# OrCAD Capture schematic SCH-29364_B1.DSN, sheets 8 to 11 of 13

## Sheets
8 C-06 BOOT CFG: size C
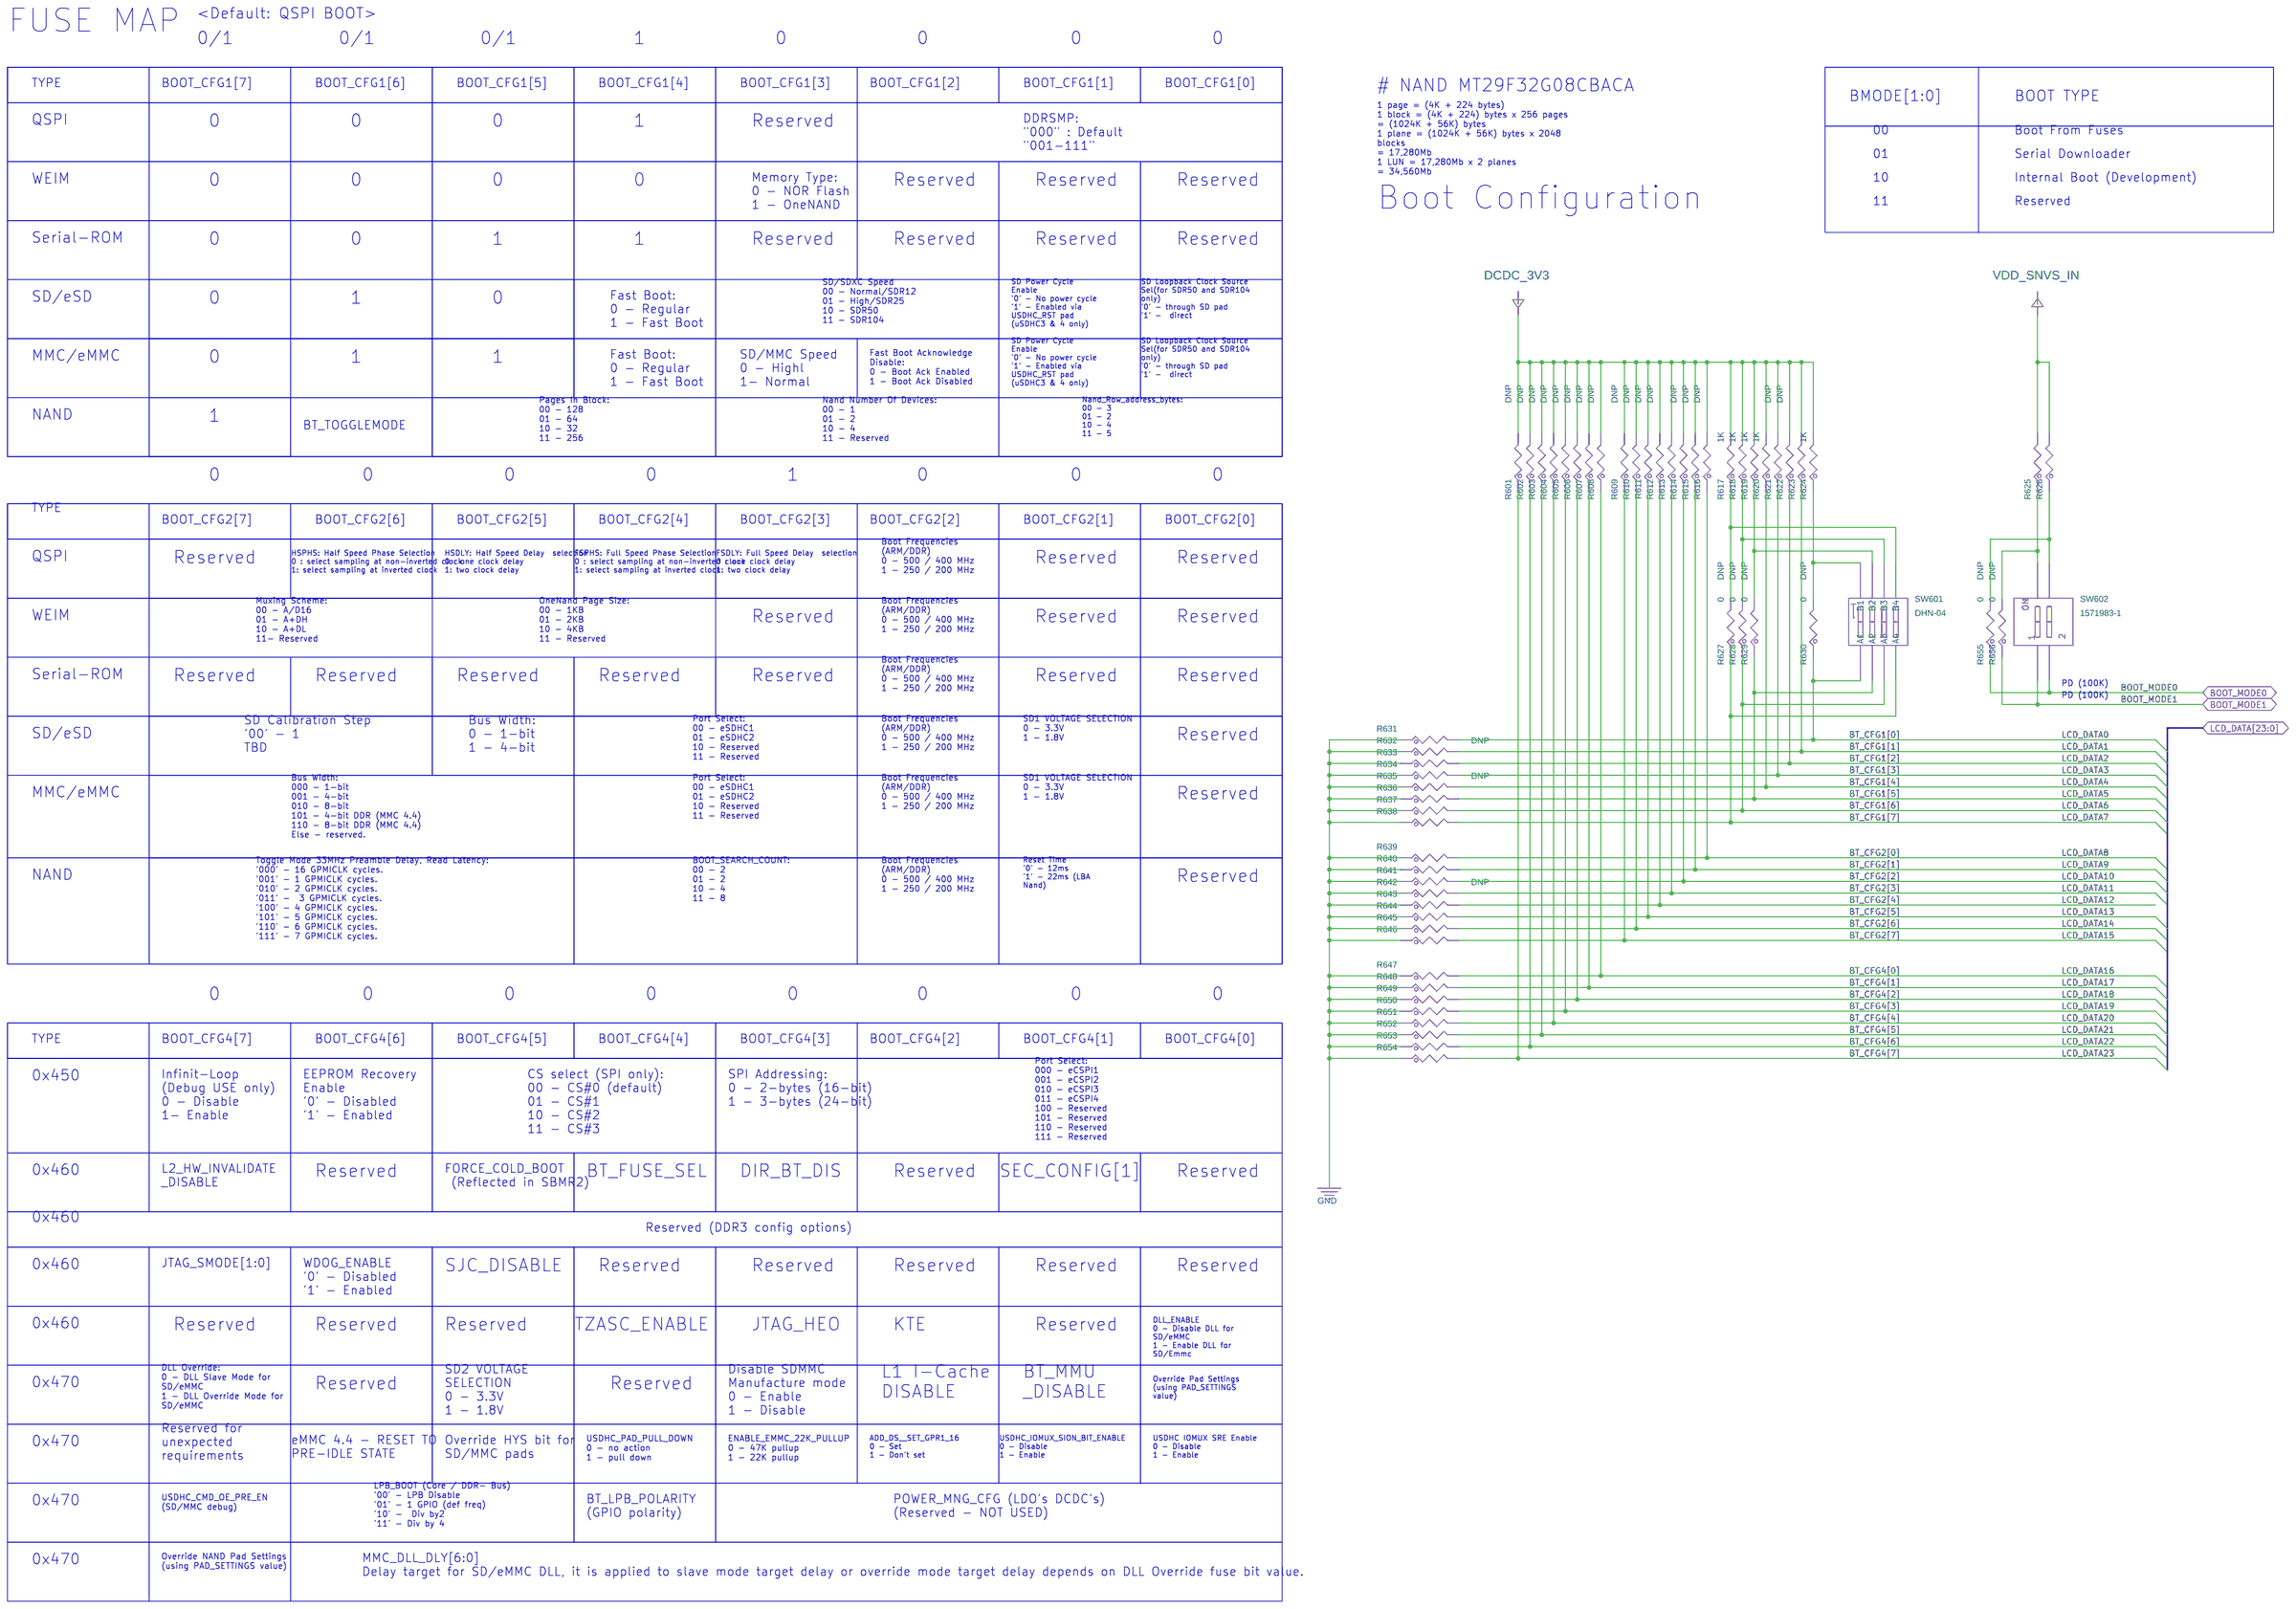
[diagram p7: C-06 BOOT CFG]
9 C-07 PWR MGR: size C
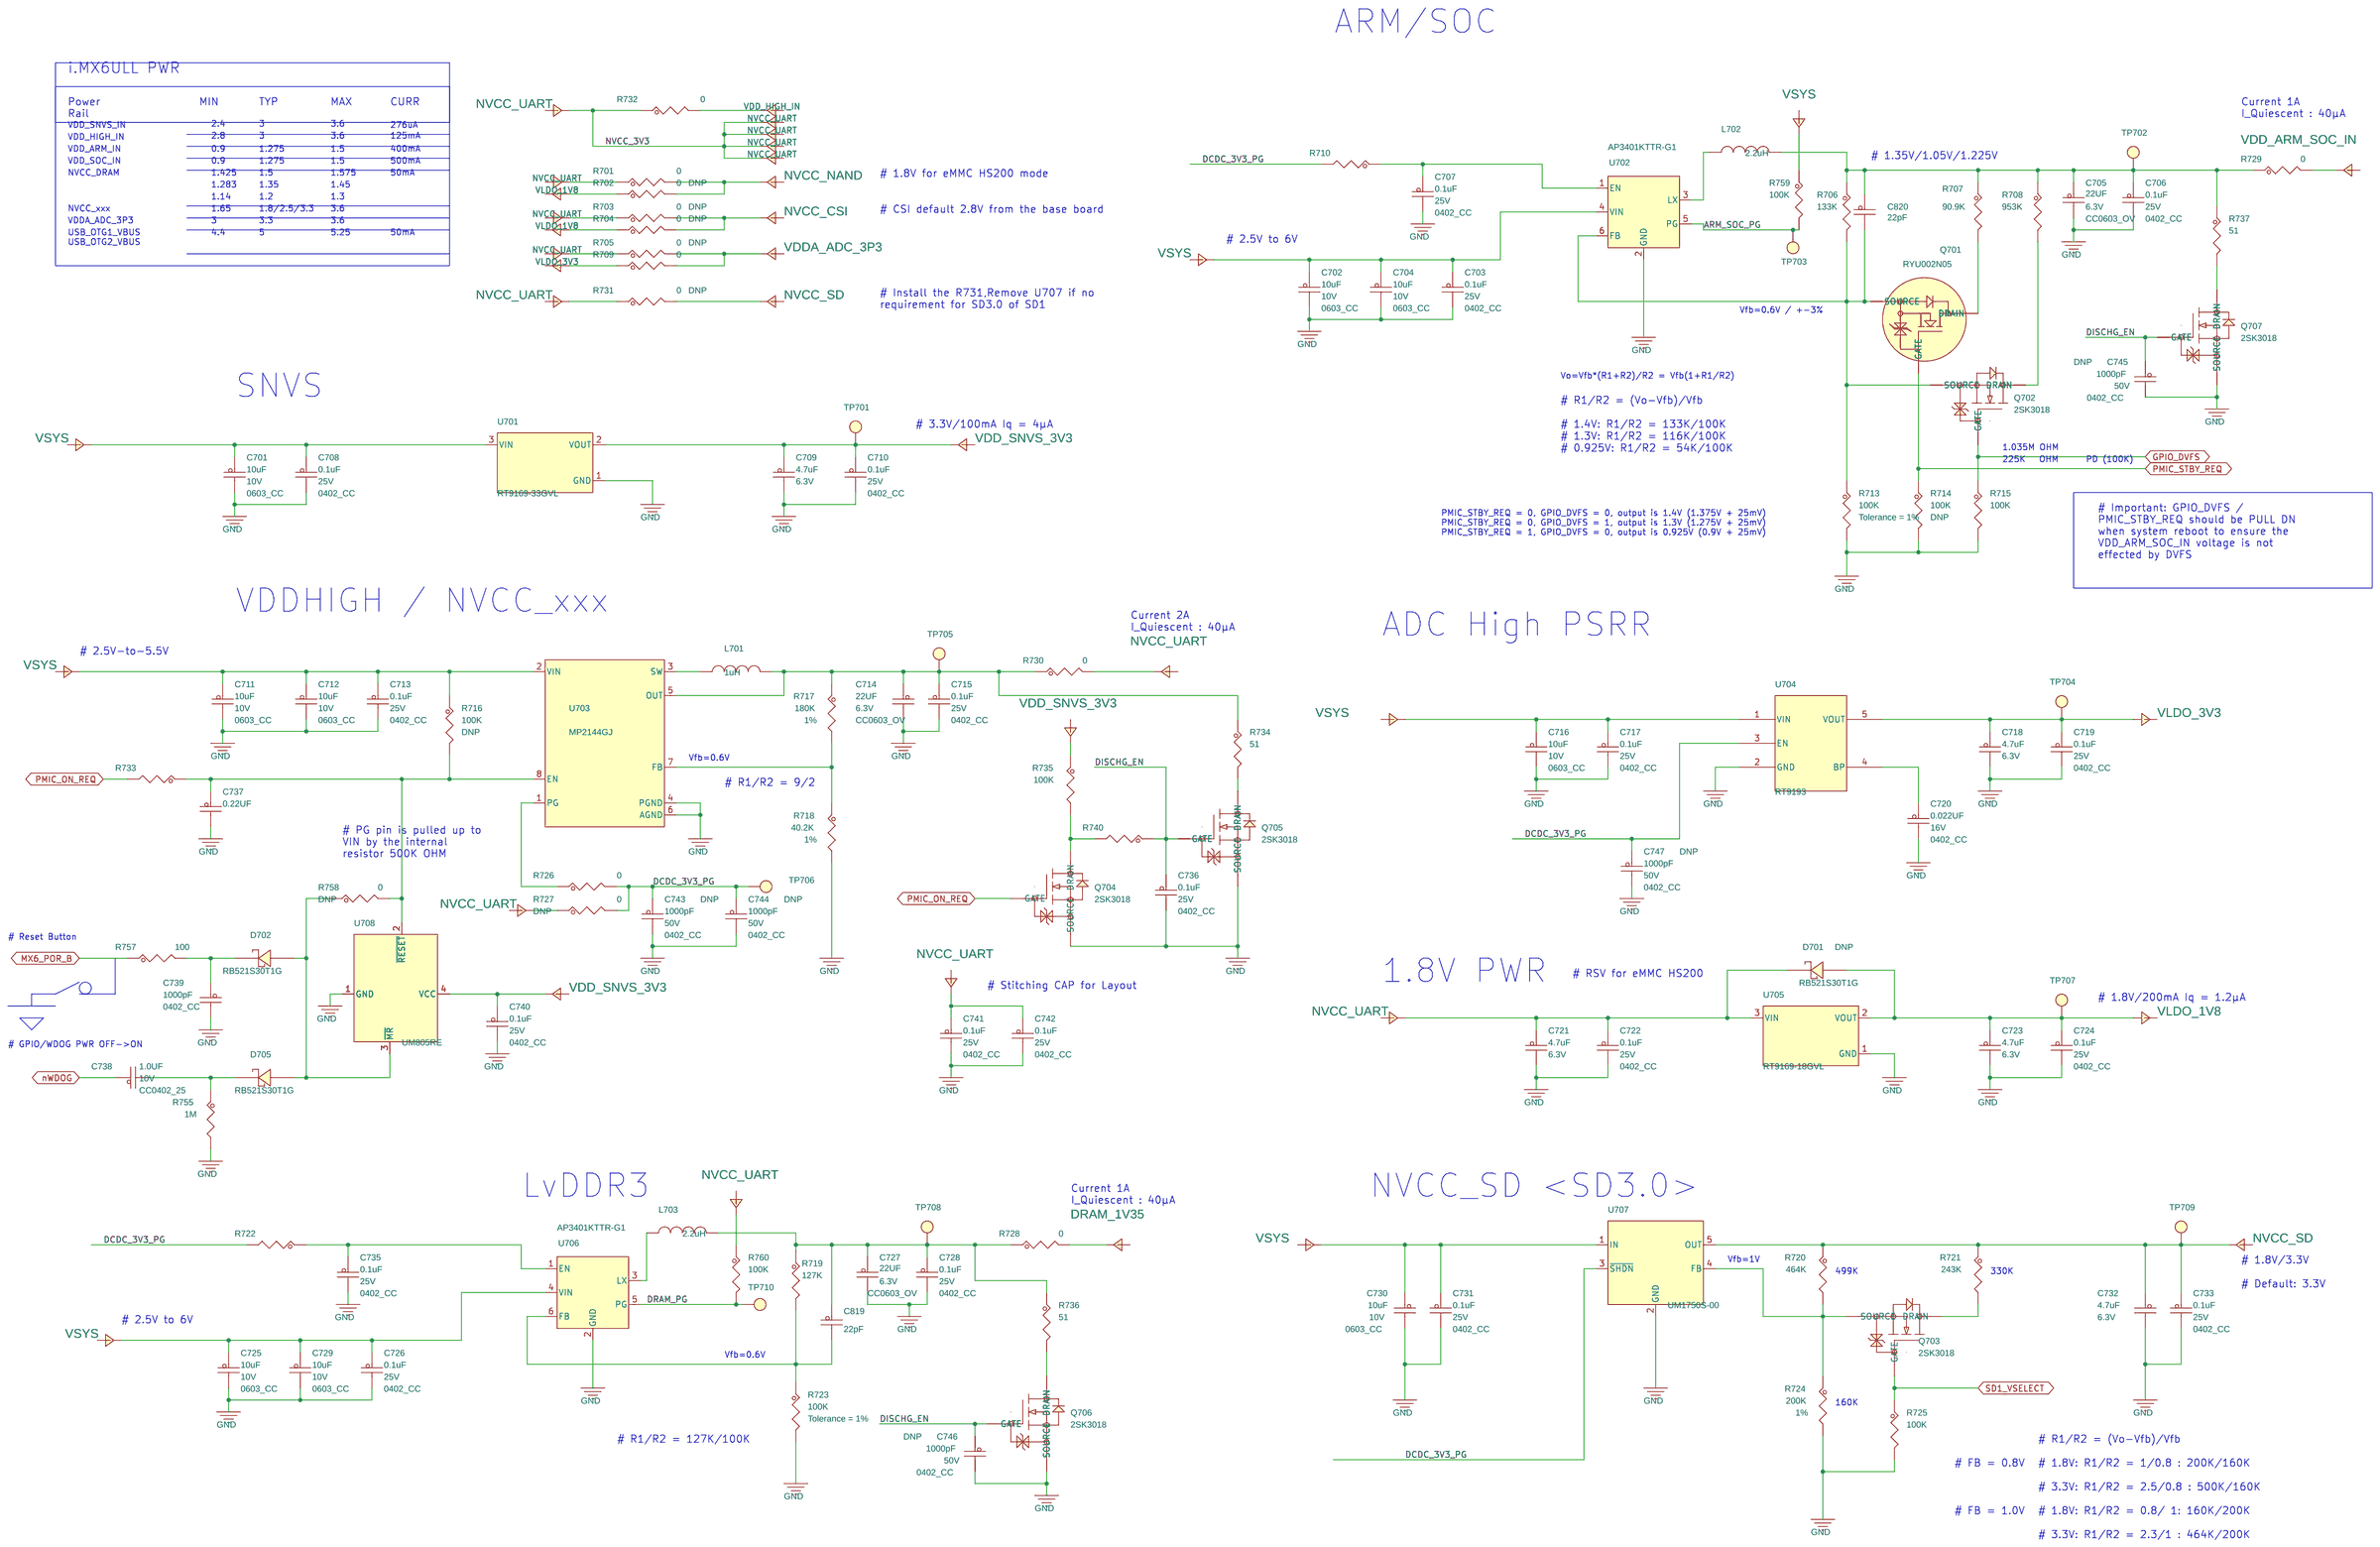
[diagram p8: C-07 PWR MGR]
10 C-08 SODIMM: size C
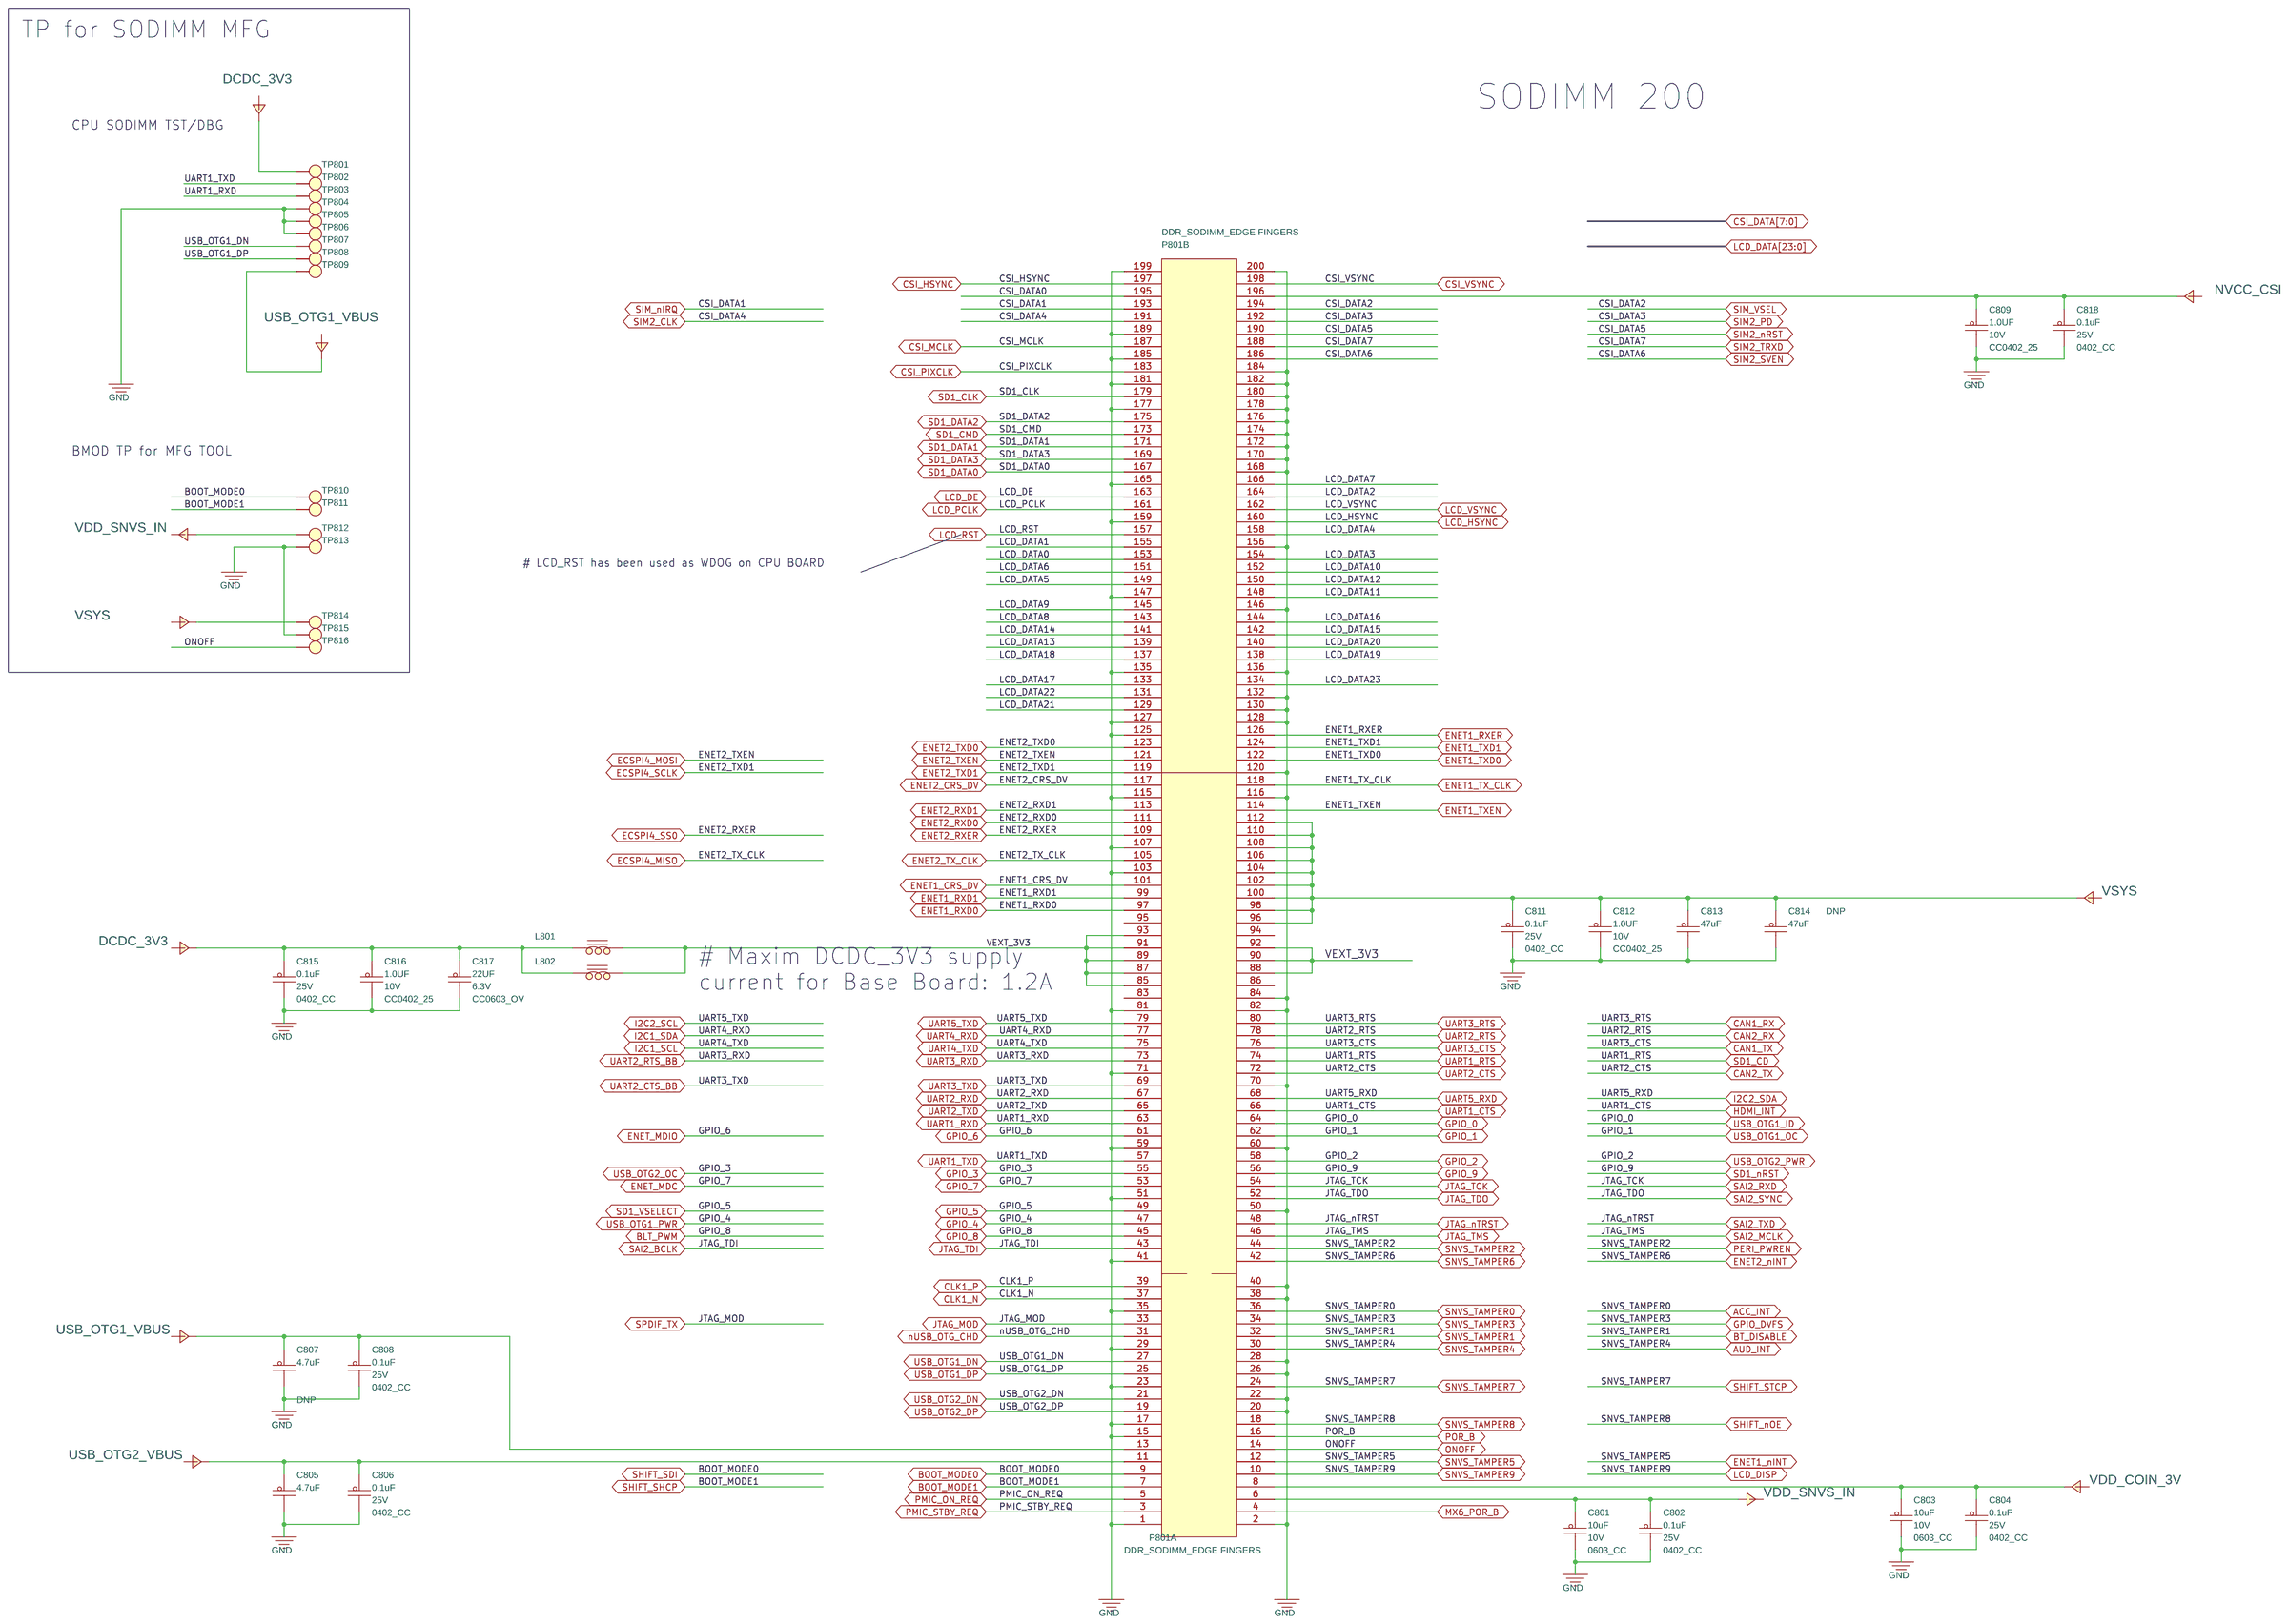
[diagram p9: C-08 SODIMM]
11 X-01 NOTE
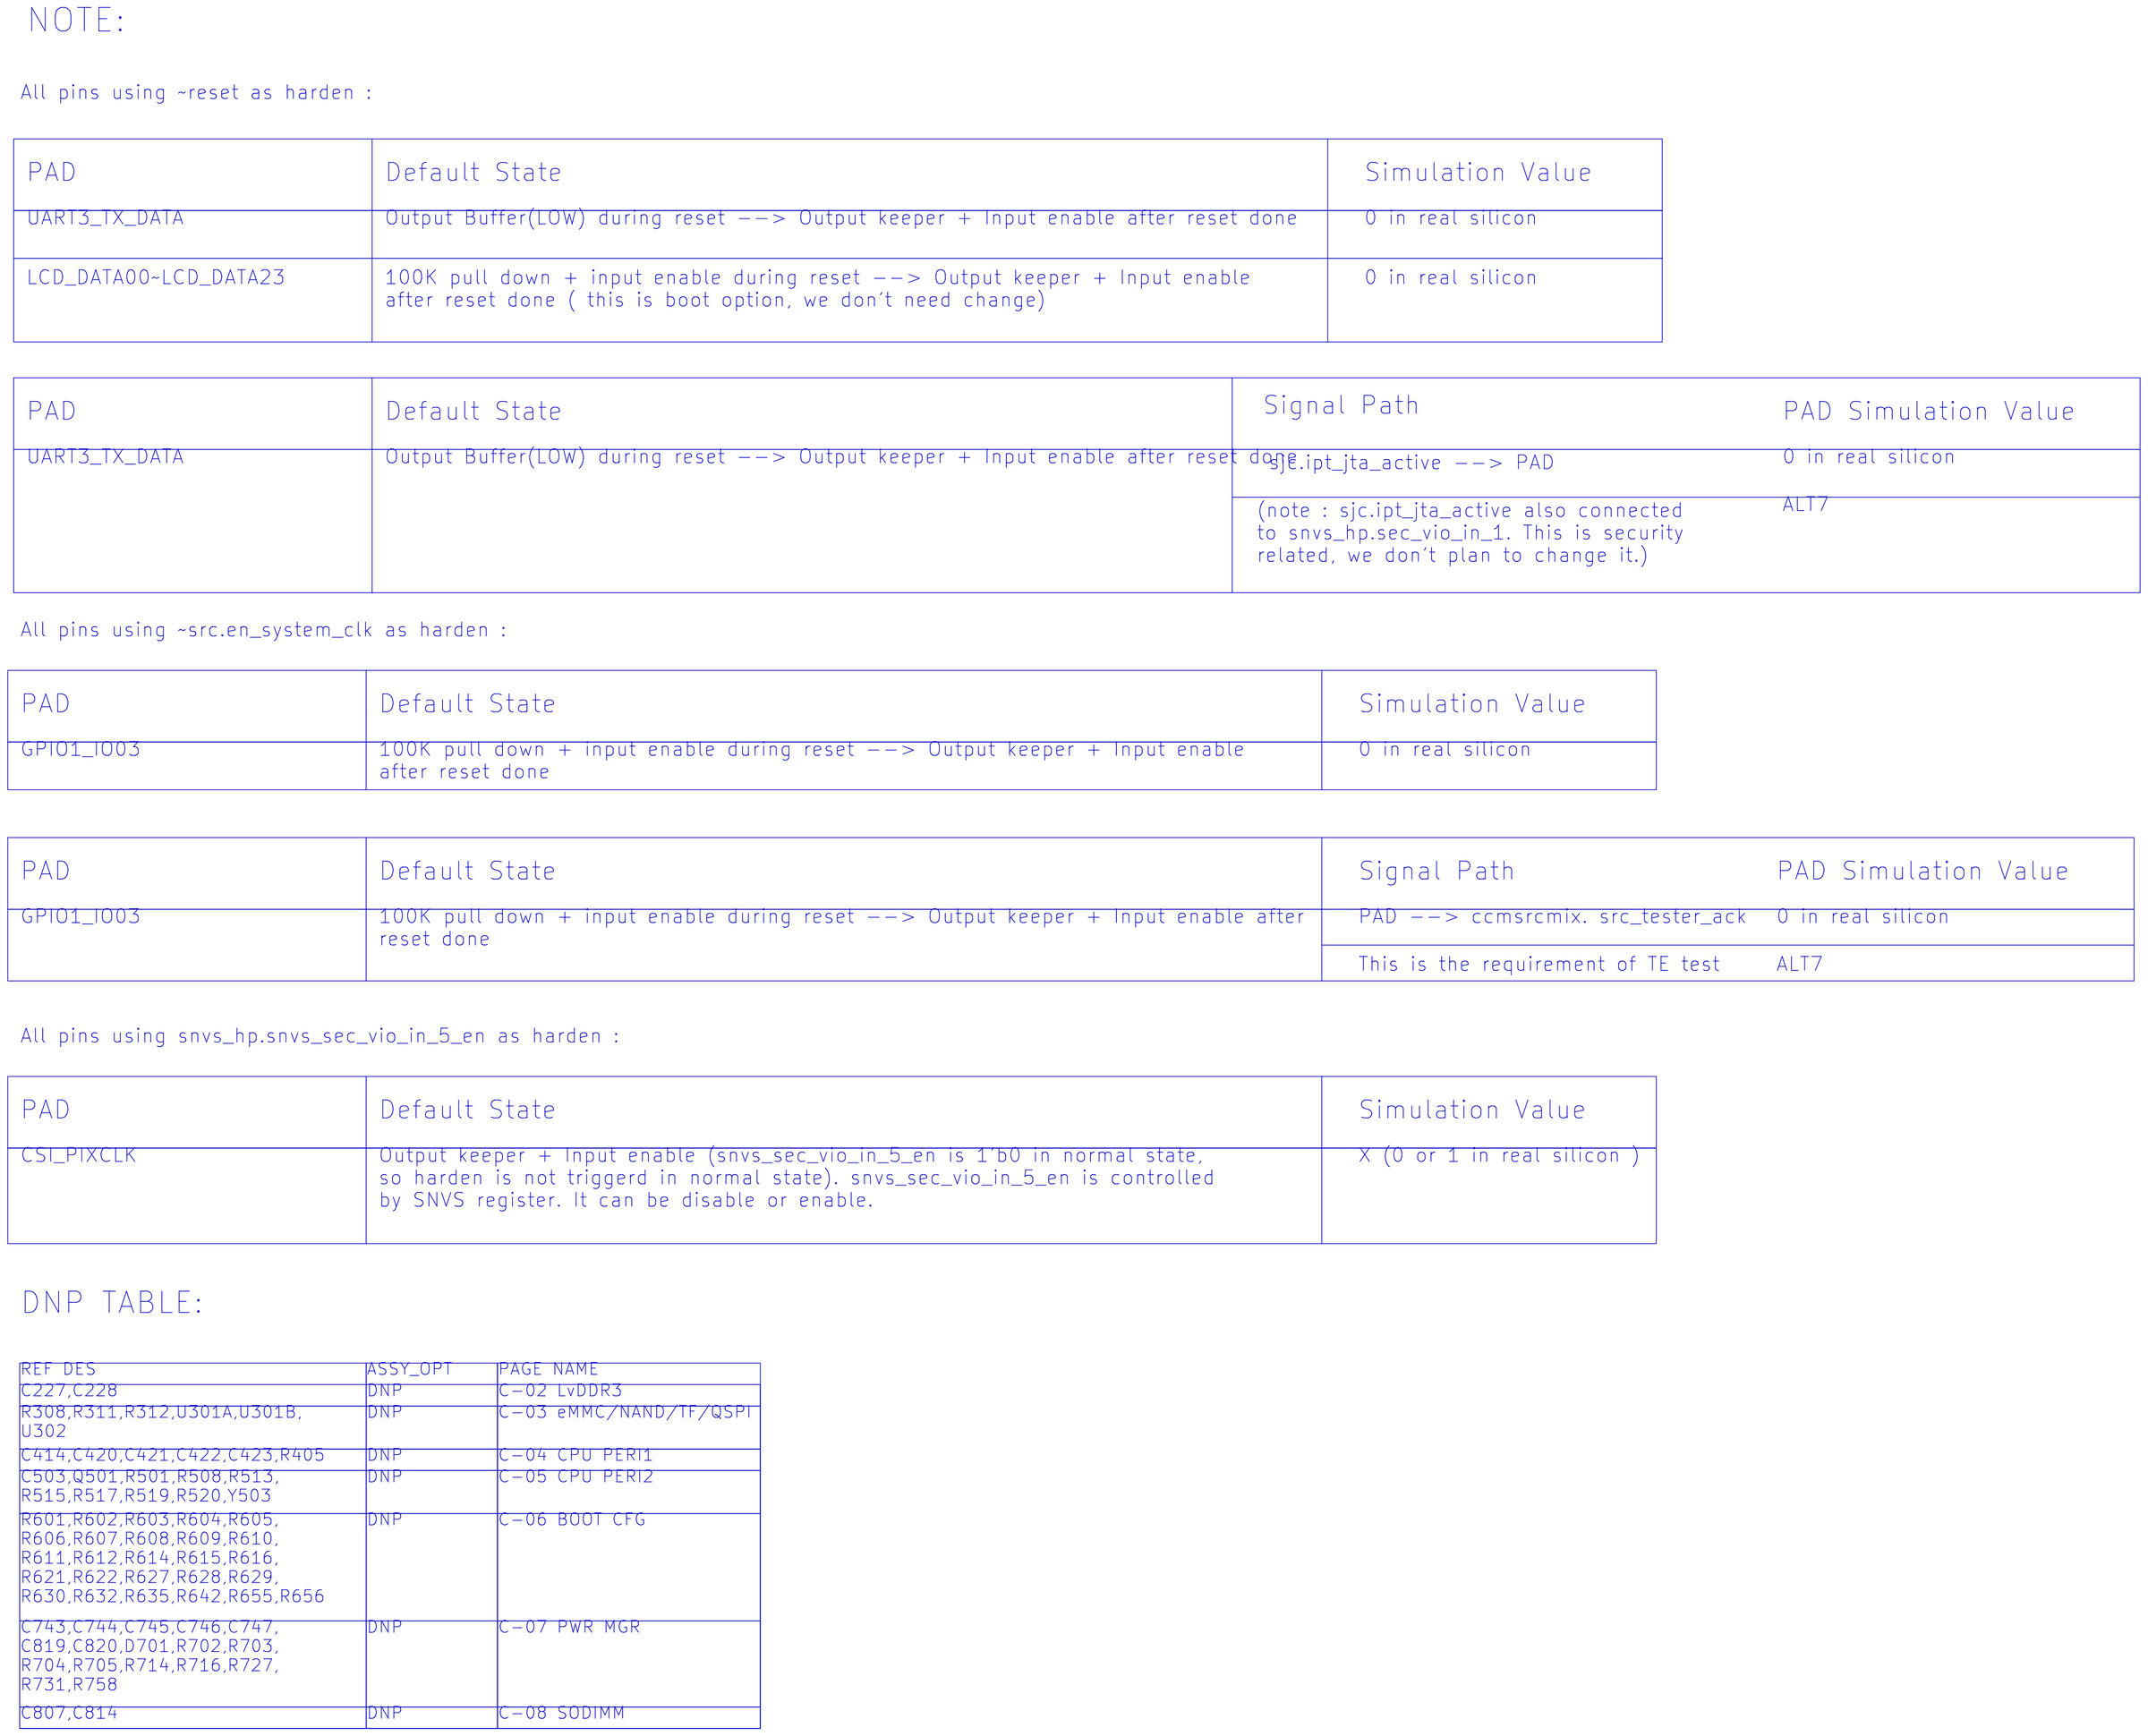
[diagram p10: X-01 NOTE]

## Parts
sheet C-06 BOOT CFG
R601  10K  [0402_CC]
R602  10K  [0402_CC]
R603  10K  [0402_CC]
R604  10K  [0402_CC]
R605  10K  [0402_CC]
R606  10K  [0402_CC]
R607  10K  [0402_CC]
R608  10K  [0402_CC]
R609  10K  [0402_CC]
R610  10K  [0402_CC]
R611  10K  [0402_CC]
R612  10K  [0402_CC]
R613  10K  [0402_CC]
R614  10K  [0402_CC]
R615  10K  [0402_CC]
R616  10K  [0402_CC]
R617  1K  [0402_CC]
R618  1K  [0402_CC]
R619  1K  [0402_CC]
R620  1K  [0402_CC]
R621  10K  [0402_CC]
R622  10K  [0402_CC]
R623  10K  [0402_CC]
R624  1K  [0402_CC]
R625  10K  [0402_CC]
R626  10K  [0402_CC]
R627  0  [0402_CC]
R628  0  [0402_CC]
R629  0  [0402_CC]
R630  0  [0402_CC]
R631  10K  [0402_CC]
R632  10K  [0402_CC]
R633  10K  [0402_CC]
R634  10K  [0402_CC]
R635  10K  [0402_CC]
R636  10K  [0402_CC]
R637  10K  [0402_CC]
R638  10K  [0402_CC]
R639  10K  [0402_CC]
R640  10K  [0402_CC]
R641  10K  [0402_CC]
R642  10K  [0402_CC]
R643  10K  [0402_CC]
R644  10K  [0402_CC]
R645  10K  [0402_CC]
R646  10K  [0402_CC]
R647  10K  [0402_CC]
R648  10K  [0402_CC]
R649  10K  [0402_CC]
R650  10K  [0402_CC]
R651  10K  [0402_CC]
R652  10K  [0402_CC]
R653  10K  [0402_CC]
R654  10K  [0402_CC]
R655  0  [0402_CC]
R656  0  [0402_CC]
SW601  DHN-04  [97C04]
SW602  1571983-1  [sw_dip2_1p27_sm]
sheet C-07 PWR MGR
C701  10uF  [0603_CC]
C702  10uF  [0603_CC]
C703  0.1uF  [0402_CC]
C704  10uF  [0603_CC]
C705  22UF  [CC0603_OV]
C706  0.1uF  [0402_CC]
C707  0.1uF  [0402_CC]
C708  0.1uF  [0402_CC]
C709  4.7uF  [cc0402_tol0p15]
C710  0.1uF  [0402_CC]
C711  10uF  [0603_CC]
C712  10uF  [0603_CC]
C713  0.1uF  [0402_CC]
C714  22UF  [CC0603_OV]
C715  0.1uF  [0402_CC]
C716  10uF  [0603_CC]
C717  0.1uF  [0402_CC]
C718  4.7uF  [cc0402_tol0p15]
C719  0.1uF  [0402_CC]
C720  0.022UF  [0402_CC]
C721  4.7uF  [cc0402_tol0p15]
C722  0.1uF  [0402_CC]
C723  4.7uF  [cc0402_tol0p15]
C724  0.1uF  [0402_CC]
C725  10uF  [0603_CC]
C726  0.1uF  [0402_CC]
C727  22UF  [CC0603_OV]
C728  0.1uF  [0402_CC]
C729  10uF  [0603_CC]
C730  10uF  [0603_CC]
C731  0.1uF  [0402_CC]
C732  4.7uF  [cc0402_tol0p15]
C733  0.1uF  [0402_CC]
C735  0.1uF  [0402_CC]
C736  0.1uF  [0402_CC]
C737  0.22UF  [0402_CC]
C738  1.0UF  [CC0402_25]
C739  1000pF  [0402_CC]
C740  0.1uF  [0402_CC]
C741  0.1uF  [0402_CC]
C742  0.1uF  [0402_CC]
C743  1000pF  [0402_CC]
C744  1000pF  [0402_CC]
C745  1000pF  [0402_CC]
C746  1000pF  [0402_CC]
C747  1000pF  [0402_CC]
C819  22pF  [0402_CC]
C820  22pF  [0402_CC]
D701  RB521S30T1G  [sod_523]
D702  RB521S30T1G  [sod_523]
D705  RB521S30T1G  [sod_523]
L701  1uH  [ind_4020]
L702  2.2uH  [ind2_sq4p31_2_sm]
L703  2.2uH  [ind2_sq4p31_2_sm]
Q701  RYU002N05  [SOT323_3]
Q702  2SK3018  [SOT323_3]
Q703  2SK3018  [SOT323_3]
Q704  2SK3018  [SOT323_3]
Q705  2SK3018  [SOT323_3]
Q706  2SK3018  [SOT323_3]
Q707  2SK3018  [SOT323_3]
R701  0  [0402_CC]
R702  0  [0402_CC]
R703  0  [0402_CC]
R704  0  [0402_CC]
R705  0  [0402_CC]
R706  133K  [0402_CC]
R707  90.9K  [0402_CC]
R708  953K  [0402_CC]
R709  0  [0402_CC]
R710  10K  [0402_CC]
R713  100K  [0402_CC]
R714  100K  [0402_CC]
R715  100K  [0402_CC]
R716  100K  [0402_CC]
R717  180K  [0402_CC]
R718  40.2K  [0402_CC]
R719  127K  [0402_CC]
R720  464K  [0402_CC]
R721  243K  [0402_CC]
R722  10K  [0402_CC]
R723  100K  [0402_CC]
R724  200K  [0402_CC]
R725  100K  [0402_CC]
R726  0  [0402_CC]
R727  0  [0402_CC]
R728  0  [RC0805_OV]
R729  0  [RC0805_OV]
R730  0  [RC0805_OV]
R731  0  [0402_CC]
R732  0  [RC0603_OV]
R733  10K  [0402_CC]
R734  51  [0402_CC]
R735  100K  [0402_CC]
R736  51  [0402_CC]
R737  51  [0402_CC]
R740  10K  [0402_CC]
R755  1M  [0402_CC]
R757  100  [0402_CC]
R758  0  [0402_CC]
R759  100K  [0402_CC]
R760  100K  [0402_CC]
TP701  TP_35MIL  [testpoint_35mil]
TP702  TP_35MIL  [testpoint_35mil]
TP703  TP_35MIL  [testpoint_35mil]
TP704  TP_35MIL  [testpoint_35mil]
TP705  TP_35MIL  [testpoint_35mil]
TP706  TP_35MIL  [testpoint_35mil]
TP707  TP_35MIL  [testpoint_35mil]
TP708  TP_35MIL  [testpoint_35mil]
TP709  TP_35MIL  [testpoint_35mil]
TP710  TP_35MIL  [testpoint_35mil]
U701  RT9169-33GVL  [sot23-3-1p95]
U702  AP3401KTTR-G1  [sot23-6]
U703  MP2144GJ  [tsot23_8_0p65_2x1]
U704  RT9193  [sot23-5]
U705  RT9169-18GVL  [sot23-3-1p95]
U706  AP3401KTTR-G1  [sot23-6]
U707  UM1750S-00  [sot23-5_a]
U708  UM805RE  [sot_143]
sheet C-08 SODIMM
C801  10uF  [0603_CC]
C802  0.1uF  [0402_CC]
C803  10uF  [0603_CC]
C804  0.1uF  [0402_CC]
C805  4.7uF  [0603_CC]
C806  0.1uF  [0402_CC]
C807  4.7uF  [0603_CC]
C808  0.1uF  [0402_CC]
C809  1.0UF  [CC0402_25]
C811  0.1uF  [0402_CC]
C812  1.0UF  [CC0402_25]
C813  47uF  [CC0805_OV]
C814  47uF  [CC0805_OV]
C815  0.1uF  [0402_CC]
C816  1.0UF  [CC0402_25]
C817  22UF  [CC0603_OV]
C818  0.1uF  [0402_CC]
L801  120OHM  [0603_CC]
L802  120OHM  [0603_CC]
P801  DDR_SODIMM_EDGE FINGERS  [SODIMM_67589]  (sections A,B)
TP801  TP_35MIL  [testpoint_35mil]
TP802  TP_35MIL  [testpoint_35mil]
TP803  TP_35MIL  [testpoint_35mil]
TP804  TP_35MIL  [testpoint_35mil]
TP805  TP_35MIL  [testpoint_35mil]
TP806  TP_35MIL  [testpoint_35mil]
TP807  TP_35MIL  [testpoint_35mil]
TP808  TP_35MIL  [testpoint_35mil]
TP809  TP_35MIL  [testpoint_35mil]
TP810  TP_35MIL  [testpoint_35mil]
TP811  TP_35MIL  [testpoint_35mil]
TP812  TP_35MIL  [testpoint_35mil]
TP813  TP_35MIL  [testpoint_35mil]
TP814  TP_35MIL  [testpoint_35mil]
TP815  TP_35MIL  [testpoint_35mil]
TP816  TP_35MIL  [testpoint_35mil]

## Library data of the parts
R601-R612 R614-R616 R621 R622 R632 R635 R642 = RES: RES MF 10K 1/16W 5% 0402; AGILE_PN: 470-75557; ASSY_OPT: DNP; CAD_APPROVED: Yes; FPLIST: RC0402_25,RC0402_HD,0402_CC; HEIGHT: 0.4 MM; MFG_NAME01: BOURNS; MFG_PN01: CR0402-JW-103GLF; ROHS: Yes; TOL: 5%; Tolerance: 5%
R613 R623 R625 R626 R631 R633 R634 R636-R641 R643-R654 = RES: RES MF 10K 1/16W 5% 0402; AGILE_PN: 470-75557; CAD_APPROVED: Yes; FPLIST: RC0402_25,RC0402_HD,0402_CC; HEIGHT: 0.4 MM; MFG_NAME01: BOURNS; MFG_PN01: CR0402-JW-103GLF; ROHS: Yes; TOL: 5%; Tolerance: 5%
R617-R620 R624 = RES: RES MF 1.0K 1/16W 5% 0402; AGILE_PN: 470-75555; CAD_APPROVED: Yes; FPLIST: RC0402_25,RC0402_HD,RC0402_X2,0402_CC; HEIGHT: 0.41mm; MFG_NAME01: BOURNS; MFG_PN01: CR0402-JW-102GLF; ROHS: Yes; Tolerance: 5%
R627-R630 R655 R656 R702-R705 R727 R731 R758 = RES: RES MF ZERO OHM 1/16W 5% 0402; AGILE_PN: 470-75394; ASSY_OPT: DNP; CAD_APPROVED: Yes; FPLIST: RC0402_25,RC0402_HD,RC0402_X2,0402_CC; HEIGHT: 0.45 MM; MFG_NAME01: YAGEO AMERICA; MFG_PN01: RC0402JR-070RL; ROHS: Yes; Temp Range: -55 to +155C; Tolerance: 5%
SW601 = SW_DIP-4_SM: SW 4P SPST DIP 25MA 24V SMT; 3D_Mechanical_Footprint_File: http://fcl.am.freescale.net/ALLEGRO/step/97c04.STEP; AGILE_PN: 510-77990; CAD_APPROVED: Yes; HEIGHT: 1.65 MM; MFG_NAME01: DIPTRONICS MANUFACTURING; MFG_PN01: DHN-04-V; ROHS: Yes; Temp Range: -40°C to +85°C
SW602 = SW_DIP-2_SMT: SW SPST DIP2 RCK 25MA 24V SMT; 3D_Mechanical_Footprint_File: http://fcl.am.freescale.net/ALLEGRO/step/sw_dip2_1p27_sm.STEP; AGILE_PN: 510-77986; CAD_APPROVED: Yes; HEIGHT: 2.56MM; MFG_NAME01: TE CONNECTIVITY LTD; ROHS: Yes
C701 C702 C704 C711 C712 C716 C725 C729 C730 C801 C803 = CAP_NP: CAP CER 10UF 10V 20% X5R 0603; AGILE_PN: 150-78609; CAD_APPROVED: Yes; FPLIST: CC0603_OV,CC0603,0603_CC; HEIGHT: 1.016MM; MFG_NAME01: TDK; MFG_PN01: C1608X5R1A106M; Package Size: 0603; Package Type: Paper Tape; ROHS: Yes; Rated Voltage: 10V; Temp Range: -55C to +85C; Tolerance: 20%; VOLTAGE: 10V
C703 C706-C708 C710 C713 C715 C717 C719 C722 C724 C726 C728 C731 C733 C735 C736 C740-C742 C802 C804 C806 C808 C811 C815 C818 = CAP_NP: CAP CER 0.1UF 25V 10% X5R 0402; AGILE_PN: 150-78633; CAD_APPROVED: Yes; FPLIST: CC0402_25,CC0402_HD,0402_CC; HEIGHT: 0.55MM; MFG_NAME01: YAGEO AMERICA; MFG_PN01: CC0402KRX5R8BB104; Package Size: 0402; ROHS: Yes; Rated Voltage: 25V; Temp Range: -55C to +85C; Tolerance: 10%; VOLTAGE: 25V
C705 C714 C727 C817 = CAP_NP: CAP CER 22UF 6.3V 20% X5R 0603; AGILE_PN: 150-78467; CAD_APPROVED: Yes; FPLIST: CC0603_OV,CC0603,0603_CC; HEIGHT: 1MM; MFG_NAME01: SAMSUNG; MFG_PN01: CL10A226MQ8NRNE; Package Size: 0603; ROHS: Yes; Rated Voltage: 6.3V; Temp Range: -55C to +85C; Tolerance: 20%; VOLTAGE: 6.3V; voltage rating: 6.3V
C709 C718 C721 C723 C732 = CAP_NP: CAP CER 4.7UF 6.3V 20% X5R 0402; AGILE_PN: 150-78463; CAD_APPROVED: Yes; FPLIST: CC0402_25,CC0402_HD,0402_CC; HEIGHT: 0.65MM; MFG_NAME01: TDK; MFG_PN01: C1005X5R0J475M; ROHS: Yes; Rated Voltage: 6.3V; Temp Range: -55C to +85C; Tolerance: 20%; VOLTAGE: 6.3V; voltage rating: 6.3V
C720 = CAP_NP: CAP CER 0.022UF 16V 10% X7R 0402; AGILE_PN: 150-30293; CAD_APPROVED: Yes; FPLIST: CC0402_25,CC0402_HD,0402_CC; HEIGHT: 0.56MM; MFG_NAME01: AVX; MFG_PN01: 0402YC223KAT2A; ROHS: Yes; Rated Voltage: 16V; Temp Range: -55C to +125C; Tolerance: 10%; VOLTAGE: 16V
C737 = CAP_NP: CAP CER 0.22UF 10V 10% X5R 0402; AGILE_PN: 150-77358; CAD_APPROVED: Yes; FPLIST: CC0402_25,CC0402_HD,0402_CC; HEIGHT: 0.55MM; MFG_NAME01: NIC COMPONENTS CORP; MFG_PN01: NMC0402X5R224K10TRPF; ROHS: Yes; Rated Voltage: 10V; Temp Range: -55C to +85C; Tolerance: 10%; VOLTAGE: 10V
C738 C809 C812 C816 = CAP_NP: CAP CER 1.0UF 10V 10% X5R 0402; AGILE_PN: 150-75772; CAD_APPROVED: Yes; FPLIST: CC0402_25,CC0402_HD,0402_CC; HEIGHT: 0.6MM; MFG_NAME01: YAGEO AMERICA; MFG_PN01: CC0402KRX5R6BB105; Package Size: 0402; ROHS: Yes; Rated Voltage: 10V; Temp Range: -55C to +85C; Tolerance: 10%; VOLTAGE: 10V
C739 = CAP_NP: CAP CER 1000PF 50V 5% C0G 0402; AGILE_PN: 150-76334; CAD_APPROVED: Yes; FPLIST: CC0402_25,CC0402_HD,0402_CC; HEIGHT: 0.55MM; MFG_NAME01: MURATA; MFG_PN01: GRM1555C1H102JA01D; Package Size: 0402; Package Type: 180mm Paper Tape; ROHS: Yes; Rated Voltage: 50V; Temp Range: -55C to +125C; Tolerance: 5%; VOLTAGE: 50V
C743-C747 = CAP_NP: CAP CER 1000PF 50V 5% C0G 0402; AGILE_PN: 150-76334; ASSY_OPT: DNP; CAD_APPROVED: Yes; FPLIST: CC0402_25,CC0402_HD,0402_CC; HEIGHT: 0.55MM; MFG_NAME01: MURATA; MFG_PN01: GRM1555C1H102JA01D; Package Size: 0402; Package Type: 180mm Paper Tape; ROHS: Yes; Rated Voltage: 50V; Temp Range: -55C to +125C; Tolerance: 5%; VOLTAGE: 50V
C819 C820 = CAP_NP: CAP CER 22pF 50V 2% C0G HIGH-Q 0402; AGILE_PN: 150-79896; CAD_APPROVED: Yes; FPLIST: CC0402_25,CC0402_HD,0402_CC,capc0402_l; HEIGHT: 0.55MM; MFG_NAME01: MURATA; MFG_PN01: GJM1555C1H220GB01D; Package Size: 0402; Package Type: 180mm Reel PAPER W8P2; ROHS: Yes; Rated Voltage: 50V; Temp Range: -55C to +125C; Tolerance: 2%
D701 = DIODE_SCHTKY: DIODE SCH 200MA 30V AEC-Q101 SOD-523; 3D_Mechanical_Footprint_File: http://fcl.am.freescale.net/ALLEGRO/step/sod_523.STEP; AGILE_PN: 480-78501; ASSY_OPT: DNP; CAD_APPROVED: Yes; HEIGHT: 0.7MM; MFG_NAME01: ON SEMICONDUCTOR; ROHS: Yes; Rated Voltage: 30V
D702 D705 = DIODE_SCHTKY: DIODE SCH 200MA 30V AEC-Q101 SOD-523; 3D_Mechanical_Footprint_File: http://fcl.am.freescale.net/ALLEGRO/step/sod_523.STEP; AGILE_PN: 480-78501; CAD_APPROVED: Yes; HEIGHT: 0.7MM; MFG_NAME01: ON SEMICONDUCTOR; ROHS: Yes; Rated Voltage: 30V
L701 = IND: IND PWR 1UH@100KHZ 2.6A 30% SMT; 3D_Mechanical_Footprint_File: http://fcl.am.freescale.net/ALLEGRO/step/ind_4020.STEP; AGILE_PN: 180-77797; CAD_APPROVED: Yes; HEIGHT: 2.2MM; MFG_NAME01: SHENZHEN SUNLORD ELECTRONICS CO., LTD; MFG_PN01: SWPA4020S1R0NT; PART_TYPE: INDUCTOR\POWER; Package Size: 4020; ROHS: Yes; TOL: 30%; Tolerance: 30%
L702 L703 = INDUCTOR: IND PWR 2.2uH@100kHz 3.25A 0.061OHM 20% SMT; 3D_Mechanical_Footprint_File: http://fcl.am.freescale.net/ALLEGRO/step/ind2_sq4p31_2_sm.step; AGILE_PN: 180-79763; CAD_APPROVED: YES; HEIGHT: 2 MM; MFG_NAME01: WURTH ELEKTRONIK EISOS GMBH & CO. KG (ELECTRONIC & ELECTROMEHANICAL COMP); MFG_PN01: 74437324022; Package Size: 4020; ROHS: Yes; Temp Range: -40C to +125C
Q701 = NMOSFET_3P_ESD_DIODE: TRAN NMOS SW 0.9V DRIVE 50V UMT3; AGILE_PN: 480-78966; CAD_APPROVED: Yes; HEIGHT: 0.9MM; MFG_NAME01: ROHM; ROHS: Yes
Q702-Q707 = 2SK3018: TRANS MOSFET N-CH 30V .1A SOT-323; AGILE_PN: 480-75317; CAD_APPROVED: Yes; HEIGHT: 0.9MM; MFG_NAME01: ROHM; MFG_PN01: 2SK3018T106; ROHS: Yes
R701 R709 R726 = RES: RES MF ZERO OHM 1/16W 5% 0402; AGILE_PN: 470-75394; CAD_APPROVED: Yes; FPLIST: RC0402_25,RC0402_HD,RC0402_X2,0402_CC; HEIGHT: 0.45 MM; MFG_NAME01: YAGEO AMERICA; MFG_PN01: RC0402JR-070RL; ROHS: Yes; Temp Range: -55 to +155C; Tolerance: 5%
R706 = RES: RES MF 133K 1/10W 1% AEC-Q200 0402; AGILE_PN: 470-81775; CAD_APPROVED: Yes; FPLIST: RC0402_25,RC0402_HD,0402_CC; HEIGHT: 0.40 MM; MFG_NAME01: KOA SPEER; MFG_PN01: RK73H1ETTP1333F; ROHS: Yes; Temp Range: -55C to +155C; Tolerance: 1%
R707 = RES: RES MF 90.9K 1/10W 1% AEC-Q200 0402; AGILE_PN: 470-31056; CAD_APPROVED: Yes; FPLIST: RC0402_25,RC0402_HD,0402_CC; HEIGHT: 0.40 MM; MFG_NAME01: KOA SPEER; MFG_PN01: RK73H1ETTP9092F; ROHS: Yes; Temp Range: -55C to +155C; Tolerance: 1%
R708 = RES: RES MF 953K 1/10W 1% AEC-Q200 0402; AGILE_PN: 470-31172; CAD_APPROVED: Yes; FPLIST: RC0402_25,RC0402_HD,0402_CC; HEIGHT: 0.40 MM; MFG_NAME01: KOA SPEER; MFG_PN01: RK73H1ETTP9533F; ROHS: Yes; Temp Range: -55C to +155C; Tolerance: 1%
R710 R722 R733 R740 = RES: RES MF 10K 1/16W 5% 0402; AGILE_PN: 470-75557; CAD_APPROVED: Yes; FPLIST: RC0402_25,RC0402_HD,0402_CC; HEIGHT: 0.4 MM; MFG_NAME01: BOURNS; MFG_PN01: CR0402-JW-103GLF; ROHS: Yes; Tolerance: 5%
R713 R723 = RES: RES MF 100K 1/16W 1% 0402; AGILE_PN: 470-76240; CAD_APPROVED: Yes; FPLIST: RC0402_25,RC0402_HD,0402_CC; HEIGHT: 0.4MM; MFG_NAME01: BOURNS; MFG_PN01: CR0402-FX-1003GLF; ROHS: Yes; Temp_Range: -55C to +155C; Tolerance: 1%
R714 R716 = RES: RES MF 100K 1/16W 5% 0402; AGILE_PN: 470-75597; ASSY_OPT: DNP; CAD_APPROVED: Yes; FPLIST: RC0402_25,RC0402_HD,0402_CC; HEIGHT: 0.40 MM; MFG_NAME01: SMEC; MFG_PN01: RC73L2Z104JTF; ROHS: Yes; Temp Range: -55C to +155C; Temp_Range: -55C to +155C; Tolerance: 5%
R715 R725 R735 R759 R760 = RES: RES MF 100K 1/16W 5% 0402; AGILE_PN: 470-75597; CAD_APPROVED: Yes; FPLIST: RC0402_25,RC0402_HD,0402_CC; HEIGHT: 0.40 MM; MFG_NAME01: SMEC; MFG_PN01: RC73L2Z104JTF; ROHS: Yes; Temp Range: -55C to +155C; Temp_Range: -55C to +155C; Tolerance: 5%
R717 = RES: RES MF 180K 1/10W 1% AEC-Q200 0402; AGILE_PN: 470-31088; CAD_APPROVED: Yes; FPLIST: RC0402_25,RC0402_HD,0402_CC; HEIGHT: 0.40 MM; MFG_NAME01: KOA SPEER; MFG_PN01: RK73H1ETTP1803F; ROHS: Yes; Temp Range: -55C to +155C; Temp_Range: -55C to +155C; Tolerance: 1%
R718 = RES: RES MF 40.2K  1/16W 1% 0402; AGILE_PN: 470-31015; CAD_APPROVED: Yes; FPLIST: RC0402_25,RC0402_HD,0402_CC; HEIGHT: 0.40 MM; MFG_NAME01: THYE MING TECH CO LTD; MFG_PN01: CR-02FL6--40K2; ROHS: Yes; Temp Range: -55C to +155C; Temp_Range: -55C to +155C; Tolerance: 1%
R719 = RES: RES MF 127K 1/10W 1% AEC-Q200 0402; AGILE_PN: 470-81774; CAD_APPROVED: Yes; FPLIST: RC0402_25,RC0402_HD,0402_CC; HEIGHT: 0.40 MM; MFG_NAME01: KOA SPEER; MFG_PN01: RK73H1ETTP1273F; ROHS: Yes; Temp Range: -55C to +155C; Tolerance: 1%
R720 = RES: RES MF 464K 1/10W 1% AEC-Q200 0402; AGILE_PN: 470-31135; CAD_APPROVED: Yes; FPLIST: RC0402_25,RC0402_HD,0402_CC; HEIGHT: 0.40 MM; MFG_NAME01: KOA SPEER; MFG_PN01: RK73H1ETTP4643F; ROHS: Yes; Temp Range: -55C to +155C; Temp_Range: -55C to +155C; Tolerance: 1%
R721 = RES: RES MF 243K 1/10W 1% AEC-Q200 0402; AGILE_PN: 470-31102; CAD_APPROVED: Yes; FPLIST: RC0402_25,RC0402_HD,0402_CC; HEIGHT: 0.40 MM; MFG_NAME01: KOA SPEER; MFG_PN01: RK73H1ETTP2433F; ROHS: Yes; Temp Range: -55C to +155C; Temp_Range: -55C to +155C; Tolerance: 1%
R724 = RES: RES MF 200K 1/10W 1% AEC-Q200 0402; AGILE_PN: 470-31093; CAD_APPROVED: Yes; FPLIST: RC0402_25,RC0402_HD,0402_CC; HEIGHT: 0.40 MM; MFG_NAME01: KOA SPEER; MFG_PN01: RK73H1ETTP2003F; ROHS: Yes; Temp Range: -55C to +155C; Temp_Range: -55C to +155C; Tolerance: 1%
R728-R730 = RES: RES MF ZERO OHM 1/8W -- 0805; AGILE_PN: 470-75442; CAD_APPROVED: Yes; FPLIST: RC0805_OV,RC0805,RC0805_OV_3P,0805_CC; HEIGHT: 0.7 MM; MFG_NAME01: YAGEO AMERICA; MFG_PN01: RC0805JR-070RL; ROHS: Yes; Temp Range: –55 °C to +155 °C; Tolerance: 5%
R732 = RES: RES MF ZERO OHM 1/10W -- 0603; AGILE_PN: 470-80866; CAD_APPROVED: Yes; FPLIST: RC0603_OV,RC0603,R603-X2,0603_CC; HEIGHT: 0.6MM; MFG_NAME01: YAGEO AMERICA; MFG_PN01: RC0603FR-070RL; ROHS: Yes; Temp Range: –55 °C to +155 °C
R734 R736 R737 = RES: RES MF 51 OHM 1/16W 1% 0402; AGILE_PN: 470-30164; CAD_APPROVED: Yes; FPLIST: RC0402_25,RC0402_HD,0402_CC; HEIGHT: 0.40 MM; MFG_NAME01: THYE MING TECH CO LTD; MFG_PN01: CR02FL6--51R; ROHS: Yes; Tolerance: 1%
R755 = RES: RES MF 1M 1/10W 5% AEC-Q200 0402; AGILE_PN: 470-79978; CAD_APPROVED: Yes; FPLIST: RC0402_25,RC0402_HD,0402_CC; HEIGHT: 0.4MM; MFG_NAME01: KOA SPEER; MFG_PN01: RK73B1ETTP105J; ROHS: Yes; Temp Range: -55&#8451; to 155&#8451;; Temp_Range: -55&#8451; to 155&#8451;; Tolerance: 5%
R757 = RES: RES MF 100 OHM 1/16W 1% 0402; AGILE_PN: 470-30454; CAD_APPROVED: Yes; FPLIST: RC0402_25,RC0402_HD,0402_CC; HEIGHT: 0.4 MM; MFG_NAME01: THYE MING TECH CO LTD; MFG_PN01: CR-02FL6--100R; ROHS: Yes; Tolerance: 1%
TP701-TP710 TP801-TP816 = T_POINT_R: TEST POINT PAD .035 SMT, no part to order; AGILE_PN: 510-75618; CAD_APPROVED: Yes; HEIGHT: 0.1MM; ROHS: Yes
U701 = RT9169_3P: IC VREG LDO 3.3V 100mA 2-6V SOT-23-3; AGILE_PN: 315-80510; CAD_APPROVED: Yes; HEIGHT: 1.295MM; MFG_NAME01: RICHTEK; ROHS: Yes; VOLTAGE: 3.3V
U702 U706 = AP3401KTTR_SOT23-6P: IC DCDC BUCK STEPDOWN 1A 2.5-5.5V SOT-23-6; 3D_Mechanical_Footprint_File: http://fcl.am.freescale.net/ALLEGRO/step/sot-23-6.STEP; AGILE_PN: 315-83860; CAD_APPROVED: Yes; HEIGHT: 1MM; MFG_NAME01: DIODES INC; ROHS: Yes; Temp Range: -40°C ~ 85°C
U703 = MP2144GJ_TSOT23_8P: IC SYNC STEP-DOWN SW 1.2MHZ 0.6V 2A 2.5-5.5V TSOT23-8; 3D_Mechanical_Footprint_File: http://fcl.am.freescale.net/ALLEGRO/step/tsot23_8_0p65_2x1.STEP; AGILE_PN: 315-80508; CAD_APPROVED: Yes; HEIGHT: 1MM; MFG_NAME01: MONOLITHIC POWER SYSTEMS; ROHS: Yes; VOLTAGE: 2.5-5.5V
U704 = RT9193-33PB: IC VREG LDO 3.3V 300MA SOT-23-5; AGILE_PN: 315-76265; CAD_APPROVED: Yes; HEIGHT: 1.295MM; MFG_NAME01: RICHTEK; ROHS: Yes
U705 = RT9169_3P: IC VREG LDO 1.8V 100mA 2-6V SOT-23-3; AGILE_PN: 315-80514; CAD_APPROVED: Yes; HEIGHT: 1.295MM; MFG_NAME01: RICHTEK; ROHS: Yes; VOLTAGE: 1.8V
U707 = UM1750S-00_5P: IC VREG LDO ADJ 1-5V 350mA 2.5-6V SOT23-5; 3D_Mechanical_Footprint_File: http://fcl.am.freescale.net/ALLEGRO/step/sot23-5_a.STEP; AGILE_PN: 315-80554; CAD_APPROVED: Yes; HEIGHT: 1.25MM; MFG_NAME01: UNION SEMICONDUCTOR, INC; ROHS: Yes; VOLTAGE: 2.5-6V
U708 = UM805_4P: IC VOLT MONITOR 2.63V VTH RST 1-5.5V SOT143; 3D_Mechanical_Footprint_File: http://fcl.am.freescale.net/ALLEGRO/step/sot_143.STEP; AGILE_PN: 315-80564; CAD_APPROVED: Yes; HEIGHT: 1.22MM; MFG_NAME01: UNION SEMICONDUCTOR, INC; ROHS: Yes; VOLTAGE: 1-5.5V
C805 = CAP_NP: CAP CER 4.7uF 16V 10% X5R 0603; AGILE_PN: 150-78976; CAD_APPROVED: Yes; FPLIST: CC0603_OV,CC0603,0603_CC; HEIGHT: 0.9 MM; MFG_NAME01: TDK; MFG_PN01: C1608X5R1C475K080AC; ROHS: Yes; Rated Voltage: 16V; Temp Range: -55C to +85C; Tolerance: 10%; VOLTAGE: 16V
C807 = CAP_NP: CAP CER 4.7uF 16V 10% X5R 0603; AGILE_PN: 150-78976; ASSY_OPT: DNP; CAD_APPROVED: Yes; FPLIST: CC0603_OV,CC0603,0603_CC; HEIGHT: 0.9 MM; MFG_NAME01: TDK; MFG_PN01: C1608X5R1C475K080AC; ROHS: Yes; Rated Voltage: 16V; Temp Range: -55C to +85C; Tolerance: 10%; VOLTAGE: 16V
C813 = CAP_NP: CAP CER 47uF 10V 20% X5R 0805; AGILE_PN: 150-78979; CAD_APPROVED: Yes; FPLIST: CC0805_OV,CC0805,0805_CC; HEIGHT: 1.45 MM; MFG_NAME01: TDK; MFG_PN01: C2012X5R1A476M125AC; ROHS: Yes; Rated Voltage: 10V; Temp Range: -55C to +85C; Tolerance: 20%; VOLTAGE: 10V
C814 = CAP_NP: CAP CER 47uF 10V 20% X5R 0805; AGILE_PN: 150-78979; ASSY_OPT: DNP; CAD_APPROVED: Yes; FPLIST: CC0805_OV,CC0805,0805_CC; HEIGHT: 1.45 MM; MFG_NAME01: TDK; MFG_PN01: C2012X5R1A476M125AC; ROHS: Yes; Rated Voltage: 10V; Temp Range: -55C to +85C; Tolerance: 20%; VOLTAGE: 10V
L801 L802 = BEAD_0: IND FER BEAD 120OHM@100MHZ 2A 25% 0603; AGILE_PN: 180-30008; CAD_APPROVED: Yes; FPLIST: IND_0603,0603_CC; HEIGHT: 0.95MM; MFG_NAME01: MURATA; MFG_PN01: BLM18PG121SH1; PART_TYPE: FERRITE; ROHS: Yes; Tolerance: 25%
P801 = CONN_EDGE_200P: 200 PIN SODIMM EDGE FINGERS -- AU FOOTPRINT ONLY, NO PART TO ORDER; AGILE_PN: 211-75329; CAD_APPROVED: Yes; HEIGHT: N/A; MFG_NAME01: GENERIC; MFG_PN01: 200SODIMM_EDGEFINGER; ROHS: Yes

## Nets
GND: C701.2 C702.2 C703.2 C704.2 C705.2 C706.2 C707.2 C708.2 C709.2 C710.2 C711.2 C712.2 C713.2 C714.2 C715.2 C716.2 C717.2 C718.2 C719.2 C720.2 C721.2 C722.2 C723.2 C724.2 C725.2 C726.2 C727.2 C728.2 C729.2 C730.2 C731.2 C732.2 C733.2 C735.2 C736.2 C737.2 C739.2 C740.2 C741.2 C742.2 C743.2 C744.2 C745.2 C746.2 C747.2 C801.2 C802.2 C803.2 C804.2 C805.2 C806.2 C807.2 C808.2 C809.2 C811.2 C812.2 C813.2 C814.2 C815.2 C816.2 C817.2 C818.2 P801.1 P801.2 P801.15 P801.17 P801.20 P801.22 P801.23 P801.26 P801.28 P801.29 P801.35 P801.38 P801.40 P801.41 P801.50 P801.51 P801.59 P801.60 P801.70 P801.71 P801.81 P801.82 P801.84 P801.103 P801.107 P801.115 P801.116 P801.120 P801.125 P801.127 P801.128 P801.130 P801.132 P801.135 P801.136 P801.146 P801.147 P801.156 P801.159 P801.165 P801.168 P801.170 P801.172 P801.174 P801.176 P801.177 P801.178 P801.180 P801.181 P801.182 P801.184 P801.185 P801.189 P801.199 P801.200 Q704.1(SOURCE) Q705.1(SOURCE) Q706.1(SOURCE) Q707.1(SOURCE) R631.1 R632.1 R633.1 R634.1 R635.1 R636.1 R637.1 R638.1 R639.1 R640.1 R641.1 R642.1 R643.1 R644.1 R645.1 R646.1 R647.1 R648.1 R649.1 R650.1 R651.1 R652.1 R653.1 R654.1 R713.2 R714.2 R715.2 R718.2 R723.2 R724.2 R725.2 R755.2 TP804.1(TP) TP805.1(TP) TP806.1(TP) TP813.1(TP) TP815.1(TP) U701.1(GND) U702.2(GND) U703.4(PGND) U703.6(AGND) U704.2(GND) U705.1(GND) U706.2(GND) U707.2(GND) U708.1(GND) ; also on sheet 4 5 6 7 13
VDD_ARM_SOC_IN: R729.2 ; also on sheet 4
VDD_COIN_3V: C803.1 C804.1 P801.8 ; also on sheet 4
VDD_HIGH_IN: R732.2 ; also on sheet 4
VDD_SNVS_3V3: C709.1 C710.1 C740.1 R735.1 TP701.1(TP) U701.2(VOUT) U708.4(VCC) ; also on sheet 4
VDD_SNVS_IN: C801.1 C802.1 P801.6 R625.2 R626.2 TP812.1(TP) ; also on sheet 4 7
VDDA_ADC_3P3: R705.2 R709.2 ; also on sheet 6
ACC_INT: P801.36 ; also on sheet 7
ARM_SOC_PG: R759.2 TP703.1(TP) U702.5(PG)
AUD_INT: P801.30 ; also on sheet 7
BLT_PWM: P801.45 ; also on sheet 6
BOOT_MODE0: P801.9 R655.1 SW602.2 TP810.1(TP) ; also on sheet 7
BOOT_MODE1: P801.7 R656.1 SW602.1 TP811.1(TP) ; also on sheet 7
BT_DISABLE: P801.32 ; also on sheet 7
CAN1_RX: P801.80 ; also on sheet 7
CAN1_TX: P801.76 ; also on sheet 7
CAN2_RX: P801.78 ; also on sheet 7
CAN2_TX: P801.72 ; also on sheet 7
CLK1_N: P801.37 ; also on sheet 7
CLK1_P: P801.39 ; also on sheet 7
CSI_DATA0: P801.195 ; also on sheet 6
CSI_DATA1: P801.193 ; also on sheet 6
CSI_DATA2: P801.194 ; also on sheet 6
CSI_DATA3: P801.192 ; also on sheet 6
CSI_DATA4: P801.191 ; also on sheet 6
CSI_DATA5: P801.190 ; also on sheet 6
CSI_DATA6: P801.186 ; also on sheet 6
CSI_DATA7: P801.188 ; also on sheet 6
CSI_HSYNC: P801.197 ; also on sheet 6
CSI_MCLK: P801.187 ; also on sheet 6 13
CSI_PIXCLK: P801.183 ; also on sheet 6 13
CSI_VSYNC: P801.198 ; also on sheet 6
DCDC_3V3: C721.1 C722.1 C741.1 C742.1 C815.1 C816.1 C817.1 D701.C L801.1 L802.1 R601.2 R602.2 R603.2 R604.2 R605.2 R606.2 R607.2 R608.2 R609.2 R610.2 R611.2 R612.2 R613.2 R614.2 R615.2 R616.2 R617.2 R618.2 R619.2 R620.2 R621.2 R622.2 R623.2 R624.2 R701.1 R703.1 R705.1 R727.1 R730.2 R731.1 R732.1 R760.1 TP801.1(TP) U705.3(VIN) ; also on sheet 6 7 13
DCDC_3V3_PG: C743.1 C744.1 C747.1 R710.2 R722.2 R726.2 R727.2 TP706.1(TP) U704.3(EN) U707.3(~{SHDN})
DISCHG_EN: C736.1 C745.1 C746.1 Q705.2(GATE) Q706.2(GATE) Q707.2(GATE) R740.1
DRAM_1V35: R728.2 ; also on sheet 5
DRAM_PG: R760.2 TP710.1(TP) U706.5(PG)
ECSPI4_MISO: P801.105 ; also on sheet 6
ECSPI4_MOSI: P801.121 ; also on sheet 6
ECSPI4_SCLK: P801.119 ; also on sheet 6
ECSPI4_SS0: P801.109 ; also on sheet 6
ENET1_CRS_DV: P801.101 ; also on sheet 6
ENET1_nINT: P801.12 ; also on sheet 7
ENET1_RXD0: P801.97 ; also on sheet 6
ENET1_RXD1: P801.99 ; also on sheet 6
ENET1_RXER: P801.126 ; also on sheet 6
ENET1_TX_CLK: P801.118 ; also on sheet 6
ENET1_TXD0: P801.122 ; also on sheet 6
ENET1_TXD1: P801.124 ; also on sheet 6
ENET1_TXEN: P801.114 ; also on sheet 6
ENET2_CRS_DV: P801.117 ; also on sheet 6
ENET2_nINT: P801.42 ; also on sheet 7
ENET2_RXD0: P801.111 ; also on sheet 6
ENET2_RXD1: P801.113 ; also on sheet 6
ENET2_TXD0: P801.123 ; also on sheet 6
ENET_MDC: P801.53 ; also on sheet 6
ENET_MDIO: P801.61 ; also on sheet 6
GPIO_0: P801.64 ; also on sheet 6
GPIO_1: P801.62 ; also on sheet 6
GPIO_2: P801.58 ; also on sheet 6
GPIO_3: P801.55 ; also on sheet 6
GPIO_4: P801.47 ; also on sheet 6
GPIO_5: P801.49 Q703.2(GATE) R725.1 ; also on sheet 6
GPIO_9: P801.56 ; also on sheet 6
GPIO_DVFS: P801.34 Q702.2(GATE) R715.1 ; also on sheet 7
HDMI_INT: P801.66 ; also on sheet 7
I2C1_SCL: P801.75 ; also on sheet 7
I2C1_SDA: P801.77 ; also on sheet 7
I2C2_SCL: P801.79 ; also on sheet 7
I2C2_SDA: P801.68 ; also on sheet 7
JTAG_MOD: P801.33 ; also on sheet 7
JTAG_nTRST: P801.48 ; also on sheet 7
JTAG_TCK: P801.54 ; also on sheet 7
JTAG_TDI: P801.43 ; also on sheet 7
JTAG_TDO: P801.52 ; also on sheet 7
JTAG_TMS: P801.46 ; also on sheet 7
LCD_DATA0: P801.153 R630.1 R631.2 SW601.1(A1) ; also on sheet 6
LCD_DATA1: P801.155 R623.1 R632.2 ; also on sheet 6
LCD_DATA2: P801.164 R622.1 R633.2 ; also on sheet 6
LCD_DATA3: P801.154 R621.1 R634.2 ; also on sheet 6
LCD_DATA4: P801.158 R620.1 R635.2 ; also on sheet 6
LCD_DATA5: P801.149 R629.1 R636.2 SW601.2(A2) ; also on sheet 6
LCD_DATA6: P801.151 R628.1 R637.2 SW601.3(A3) ; also on sheet 6
LCD_DATA7: P801.166 R627.1 R638.2 SW601.4(A4) ; also on sheet 6
LCD_DATA8: P801.143 R616.1 R639.2 ; also on sheet 6
LCD_DATA9: P801.145 R615.1 R640.2 ; also on sheet 6
LCD_DATA10: P801.152 R614.1 R641.2 ; also on sheet 6
LCD_DATA11: P801.148 R613.1 R642.2 ; also on sheet 6
LCD_DATA12: P801.150 R612.1 R643.2 ; also on sheet 6
LCD_DATA13: P801.139 R611.1 R644.2 ; also on sheet 6
LCD_DATA14: P801.141 R610.1 R645.2 ; also on sheet 6
LCD_DATA15: P801.142 R609.1 R646.2 ; also on sheet 6
LCD_DATA16: P801.144 R608.1 R647.2 ; also on sheet 6
LCD_DATA17: P801.133 R607.1 R648.2 ; also on sheet 6
LCD_DATA18: P801.137 R606.1 R649.2 ; also on sheet 6
LCD_DATA19: P801.138 R605.1 R650.2 ; also on sheet 6
LCD_DATA20: P801.140 R604.1 R651.2 ; also on sheet 6
LCD_DATA21: P801.129 R603.1 R652.2 ; also on sheet 6
LCD_DATA22: P801.131 R602.1 R653.2 ; also on sheet 6
LCD_DATA23: P801.134 R601.1 R654.2 ; also on sheet 6
LCD_DE: P801.163 ; also on sheet 6
LCD_DISP: P801.10 ; also on sheet 7
LCD_HSYNC: P801.160 ; also on sheet 6
LCD_PCLK: P801.161 ; also on sheet 6
LCD_RST: P801.157 ; also on sheet 6
LCD_VSYNC: P801.162 ; also on sheet 6
MX6_POR_B: P801.4 R757.1
nUSB_OTG_CHD: P801.31 ; also on sheet 6
NVCC_CSI: C809.1 C818.1 P801.196 R703.2 R704.2 ; also on sheet 6
NVCC_NAND: R701.2 R702.2 ; also on sheet 6 13
NVCC_SD: C732.1 C733.1 R720.1 R721.1 R731.2 TP709.1(TP) U707.5(OUT) ; also on sheet 6
nWDOG: C738.1 ; also on sheet 6
ONOFF: P801.14 TP816.1(TP) ; also on sheet 7
PERI_PWREN: P801.44 ; also on sheet 7
PMIC_ON_REQ: P801.5 Q704.2(GATE) R733.2 ; also on sheet 7
PMIC_STBY_REQ: P801.3 Q701.2(GATE) R714.1 ; also on sheet 7
POR_B: P801.16 ; also on sheet 7
SD1_CD: P801.74 ; also on sheet 7
SD1_CLK: P801.179 ; also on sheet 6
SD1_CMD: P801.173 ; also on sheet 6
SD1_DATA0: P801.167 ; also on sheet 6
SD1_DATA1: P801.171 ; also on sheet 6
SD1_DATA2: P801.175 ; also on sheet 6
SD1_DATA3: P801.169 ; also on sheet 6
SHIFT_nOE: P801.18 ; also on sheet 7
SHIFT_STCP: P801.24 ; also on sheet 7
UART1_RXD: P801.63 TP803.1(TP) ; also on sheet 7
UART1_TXD: P801.57 TP802.1(TP) ; also on sheet 7
UART2_CTS_BB: P801.69 ; also on sheet 7
UART2_RTS_BB: P801.73 ; also on sheet 7
UART2_RXD: P801.67 ; also on sheet 7
UART2_TXD: P801.65 ; also on sheet 7
USB_OTG1_DN: P801.27 TP807.1(TP) ; also on sheet 6
USB_OTG1_DP: P801.25 TP808.1(TP) ; also on sheet 6
USB_OTG1_VBUS: C807.1 C808.1 P801.13 TP809.1(TP) ; also on sheet 6
USB_OTG2_DN: P801.21 ; also on sheet 6
USB_OTG2_DP: P801.19 ; also on sheet 6
USB_OTG2_VBUS: C805.1 C806.1 P801.11 ; also on sheet 6
VEXT_3V3: L801.2 L802.2 P801.85 P801.87 P801.88 P801.89 P801.90 P801.91 P801.92 P801.93
VLDO_1V8: C723.1 C724.1 D701.A R702.1 R704.1 TP707.1(TP) U705.2(VOUT)
VLDO_3V3: C718.1 C719.1 R709.1 TP704.1(TP) U704.5(VOUT)
VSYS: C701.1 C702.1 C703.1 C704.1 C708.1 C711.1 C712.1 C713.1 C716.1 C717.1 C725.1 C726.1 C729.1 C730.1 C731.1 C811.1 C812.1 C813.1 C814.1 P801.96 P801.98 P801.100 P801.102 P801.104 P801.106 P801.108 P801.110 P801.112 R716.1 R759.1 TP814.1(TP) U701.3(VIN) U702.4(VIN) U703.2(VIN) U704.1(VIN) U706.4(VIN) U707.1(IN)
N470460: C727.1 C728.1 C819.1 L703.2 R719.1 R728.1 R736.1 TP708.1(TP)
N470472: C819.2 R719.2 R723.1 U706.6(FB)
N475886: C705.1 C706.1 C820.1 L702.2 R706.1 R707.1 R708.1 R729.1 R737.1 TP702.1(TP)
N475908: C820.2 Q701.1(SOURCE) Q702.1(SOURCE) R706.2 R713.1 U702.6(FB)
N476046: L702.1 U702.3(LX)
N476911: Q701.3(DRAIN) R707.2
N477774: Q702.3(DRAIN) R708.2
N482885: R726.1 U703.1(PG)
N482959: C714.1 C715.1 L701.2 R717.1 R730.1 R734.1 TP705.1(TP) U703.5(OUT)
N483005: R717.2 R718.1 U703.7(FB)
N483147: L701.1 U703.3(SW)
N535963: C720.1 U704.4(BP)
N549057: C737.1 R716.2 R733.1 R758.2 U703.8(EN) U708.2(~{RESET})
N560035: C735.1 R722.1 U706.1(EN)
N97352648: R618.1 R628.2 SW601.6(B3)
N97352650: R617.1 R627.2 SW601.5(B4)
N97352656: R619.1 R629.2 SW601.7(B2)
N97352662: R624.1 R630.2 SW601.8(B1)
N97516911: Q703.3(DRAIN) R721.2
N97552352: Q703.1(SOURCE) R720.2 R724.1 U707.4(FB)
N97596057: R625.1 R656.2 SW602.4
N97596081: R626.1 R655.2 SW602.3
N98468969: Q704.3(DRAIN) R735.2 R740.2
N98472195: Q705.3(DRAIN) R734.2
N98472663: Q706.3(DRAIN) R736.2
N98473370: Q707.3(DRAIN) R737.2
N98716241: C739.1 D702.C R757.2
N98716244: D702.A D705.A R758.1 U708.3(~{MR})
N98738134: C738.2 D705.C R755.1
N100035660: C707.1 R710.1 U702.1(EN)
N100054789: L703.1 U706.3(LX)

Not connected (* = marked no-connect by the designer): P801 83 86 94 95

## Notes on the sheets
sheet 8
- FUSE MAP
- <Default: QSPI BOOT>
- 0/1
- 0/1
- 0/1
- 1
- 0
- 0
- 0
- 0
- TYPE
- BOOT_CFG1[7]
- BOOT_CFG1[6]
- BOOT_CFG1[5]
- BOOT_CFG1[4]
- BOOT_CFG1[3]
- BOOT_CFG1[2]
- BOOT_CFG1[1]
- BOOT_CFG1[0]
- # NAND MT29F32G08CBACA
- BMODE[1:0]
- BOOT TYPE
- 1 page = (4K + 224 bytes)
  1 block = (4K + 224) bytes x 256 pages
  = (1024K + 56K) bytes
  1 plane = (1024K + 56K) bytes x 2048
  blocks
  = 17,280Mb
  1 LUN = 17,280Mb x 2 planes
  = 34,560Mb
- QSPI
- 0
- 0
- 0
- 1
- Reserved
- DDRSMP:
  "000" : Default
  "001-111"
- 00
- Boot From Fuses
- 01
- Serial Downloader
- WEIM
- 0
- 0
- 0
- 0
- Memory Type:
  0 - NOR Flash
  1 - OneNAND
- Reserved
- Reserved
- Reserved
- 10
- Internal Boot (Development)
- Boot Configuration
- 11
- Reserved
- Serial-ROM
- 0
- 0
- 1
- 1
- Reserved
- Reserved
- Reserved
- Reserved
- SD/SDXC Speed
  00 - Normal/SDR12
  01 - High/SDR25
  10 - SDR50
  11 - SDR104
- SD Power Cycle
  Enable
  '0' - No power cycle
  '1' - Enabled via
  USDHC_RST pad
  (uSDHC3 & 4 only)
- SD Loopback Clock Source
  Sel(for SDR50 and SDR104
  only)
  '0' - through SD pad
  '1' -  direct
- SD/eSD
- 0
- 1
- 0
- Fast Boot:
  0 - Regular
  1 - Fast Boot
- MMC/eMMC
- 0
- 1
- 1
- Fast Boot:
  0 - Regular
  1 - Fast Boot
- SD/MMC Speed
  0 - Highl
  1- Normal
- Fast Boot Acknowledge
  Disable:
  0 - Boot Ack Enabled
  1 - Boot Ack Disabled
- SD Power Cycle
  Enable
  '0' - No power cycle
  '1' - Enabled via
  USDHC_RST pad
  (uSDHC3 & 4 only)
- SD Loopback Clock Source
  Sel(for SDR50 and SDR104
  only)
  '0' - through SD pad
  '1' -  direct
- Pages In Block:
  00 - 128
  01 - 64
  10 - 32
  11 - 256
- Nand Number Of Devices:
  00 - 1
  01 - 2
  10 - 4
  11 - Reserved
- Nand_Row_address_bytes:
  00 - 3
  01 - 2
  10 - 4
  11 - 5
- NAND
- 1
- BT_TOGGLEMODE
- 0
- 0
- 0
- 0
- 1
- 0
- 0
- 0
- TYPE
- BOOT_CFG2[7]
- BOOT_CFG2[6]
- BOOT_CFG2[5]
- BOOT_CFG2[4]
- BOOT_CFG2[3]
- BOOT_CFG2[2]
- BOOT_CFG2[1]
- BOOT_CFG2[0]
- Boot Frequencies
  (ARM/DDR)
  0 - 500 / 400 MHz
  1 - 250 / 200 MHz
- QSPI
- Reserved
- HSPHS: Half Speed Phase Selection
  0 : select sampling at non-inverted clock
  1: select sampling at inverted clock
- HSDLY: Half Speed Delay  selection
  0 : one clock delay
  1: two clock delay
- FSPHS: Full Speed Phase Selection
  0 : select sampling at non-inverted clock
  1: select sampling at inverted clock
- FSDLY: Full Speed Delay  selection
  0 : one clock delay
  1: two clock delay
- Reserved
- Reserved
- Muxing Scheme:
  00 - A/D16
  01 - A+DH
  10 - A+DL
  11- Reserved
- OneNand Page Size:
  00 - 1KB
  01 - 2KB
  10 - 4KB
  11 - Reserved
- Boot Frequencies
  (ARM/DDR)
  0 - 500 / 400 MHz
  1 - 250 / 200 MHz
- WEIM
- Reserved
- Reserved
- Reserved
- Boot Frequencies
  (ARM/DDR)
  0 - 500 / 400 MHz
  1 - 250 / 200 MHz
- Serial-ROM
- Reserved
- Reserved
- Reserved
- Reserved
- Reserved
- Reserved
- Reserved
- PD (100K)
- PD (100K)
- SD Calibration Step
  '00' - 1
  TBD
- Bus Width:
  0 - 1-bit
  1 - 4-bit
- Port Select:
  00 - eSDHC1
  01 - eSDHC2
  10 - Reserved
  11 - Reserved
- Boot Frequencies
  (ARM/DDR)
  0 - 500 / 400 MHz
  1 - 250 / 200 MHz
- SD1 VOLTAGE SELECTION
  0 - 3.3V
  1 - 1.8V
- SD/eSD
- Reserved
- Bus Width:
  000 - 1-bit
  001 - 4-bit
  010 - 8-bit
  101 - 4-bit DDR (MMC 4.4)
  110 - 8-bit DDR (MMC 4.4)
  Else - reserved.
- Port Select:
  00 - eSDHC1
  01 - eSDHC2
  10 - Reserved
  11 - Reserved
- Boot Frequencies
  (ARM/DDR)
  0 - 500 / 400 MHz
  1 - 250 / 200 MHz
- SD1 VOLTAGE SELECTION
  0 - 3.3V
  1 - 1.8V
- MMC/eMMC
- Reserved
- Toggle Mode 33MHz Preamble Delay, Read Latency:
  '000' - 16 GPMICLK cycles.
  '001' - 1 GPMICLK cycles.
  '010' - 2 GPMICLK cycles.
  '011' -  3 GPMICLK cycles.
  '100' - 4 GPMICLK cycles.
  '101' - 5 GPMICLK cycles.
  '110' - 6 GPMICLK cycles.
  '111' - 7 GPMICLK cycles.
- BOOT_SEARCH_COUNT:
  00 - 2
  01 - 2
  10 - 4
  11 - 8
- Boot Frequencies
  (ARM/DDR)
  0 - 500 / 400 MHz
  1 - 250 / 200 MHz
- Reset Time
  '0' - 12ms
  '1' - 22ms (LBA
  Nand)
- NAND
- Reserved
- 0
- 0
- 0
- 0
- 0
- 0
- 0
- 0
- TYPE
- BOOT_CFG4[7]
- BOOT_CFG4[6]
- BOOT_CFG4[5]
- BOOT_CFG4[4]
- BOOT_CFG4[3]
- BOOT_CFG4[2]
- BOOT_CFG4[1]
- BOOT_CFG4[0]
- Port Select:
  000 - eCSPI1
  001 - eCSPI2
  010 - eCSPI3
  011 - eCSPI4
  100 - Reserved
  101 - Reserved
  110 - Reserved
  111 - Reserved
- 0x450
- Infinit-Loop
  (Debug USE only)
  0 - Disable
  1- Enable
- EEPROM Recovery
  Enable
  '0' - Disabled
  '1' - Enabled
- CS select (SPI only):
  00 - CS#0 (default)
  01 - CS#1
  10 - CS#2
  11 - CS#3
- SPI Addressing:
  0 - 2-bytes (16-bit)
  1 - 3-bytes (24-bit)
- 0x460
- L2_HW_INVALIDATE
  _DISABLE
- Reserved
- FORCE_COLD_BOOT
   (Reflected in SBMR2)
- BT_FUSE_SEL
- DIR_BT_DIS
- Reserved
- SEC_CONFIG[1]
- Reserved
- 0x460
- Reserved (DDR3 config options)
- 0x460
- JTAG_SMODE[1:0]
- WDOG_ENABLE
  '0' - Disabled
  '1' - Enabled
- SJC_DISABLE
- Reserved
- Reserved
- Reserved
- Reserved
- Reserved
- 0x460
- Reserved
- Reserved
- Reserved
- TZASC_ENABLE
- JTAG_HEO
- KTE
- Reserved
- DLL_ENABLE
  0 - Disable DLL for
  SD/eMMC
  1 - Enable DLL for
  SD/Emmc
- DLL Override:
  0 - DLL Slave Mode for
  SD/eMMC
  1 - DLL Override Mode for
  SD/eMMC
- SD2 VOLTAGE
  SELECTION
  0 - 3.3V
  1 - 1.8V
- Disable SDMMC
  Manufacture mode
  0 - Enable
  1 - Disable
- L1 I-Cache
  DISABLE
- BT_MMU
  _DISABLE
- 0x470
- Reserved
- Reserved
- Override Pad Settings
  (using PAD_SETTINGS
  value)
- 0x470
- Reserved for
  unexpected
  requirements
- eMMC 4.4 - RESET TO
  PRE-IDLE STATE
- Override HYS bit for
  SD/MMC pads
- USDHC_PAD_PULL_DOWN
  0 - no action
  1 - pull down
- ENABLE_EMMC_22K_PULLUP
  0 - 47K pullup
  1 - 22K pullup
- ADD_DS__SET_GPR1_16
  0 - Set
  1 - Don't set
- USDHC_IOMUX_SION_BIT_ENABLE
  0 - Disable
  1 - Enable
- USDHC IOMUX SRE Enable
  0 - Disable
  1 - Enable
- LPB_BOOT (Core / DDR- Bus)
  '00' - LPB Disable
  '01' - 1 GPIO (def freq)
  '10' -  Div by2
  '11' - Div by 4
- 0x470
- USDHC_CMD_OE_PRE_EN
  (SD/MMC debug)
- BT_LPB_POLARITY
  (GPIO polarity)
- POWER_MNG_CFG (LDO's DCDC's)
  (Reserved - NOT USED)
- 0x470
- Override NAND Pad Settings
  (using PAD_SETTINGS value)
- MMC_DLL_DLY[6:0]
  Delay target for SD/eMMC DLL, it is applied to slave mode target delay or override mode target delay depends on DLL Override fuse bit value.
sheet 9
- ARM/SOC
- i.MX6ULL PWR
- Power
  Rail
- MIN
- TYP
- MAX
- CURR
- Current 1A
  I_Quiescent : 40μA
- VDD_SNVS_IN
- 2.4
- 3
- 3.6
- 276uA
- VDD_HIGH_IN
- 2.8
- 3
- 3.6
- 125mA
- VDD_ARM_IN
- 0.9
- 1.275
- 1.5
- 400mA
- VDD_SOC_IN
- 0.9
- 1.275
- 1.5
- 500mA
- # 1.35V/1.05V/1.225V
- NVCC_DRAM
- 1.425
- 1.5
- 1.575
- 50mA
- # 1.8V for eMMC HS200 mode
- 1.14
- 1.283
- 1.2
- 1.35
- 1.3
- 1.45
- NVCC_xxx
- 1.65
- 1.8/2.5/3.3
- 3.6
- # CSI default 2.8V from the base board
- VDDA_ADC_3P3
- 3
- 3.3
- 3.6
- USB_OTG1_VBUS
  USB_OTG2_VBUS
- 4.4
- 5
- 5.25
- 50mA
- # 2.5V to 6V
- # Install the R731,Remove U707 if no
  requirement for SD3.0 of SD1
- Vfb=0.6V / +-3%
- SNVS
- Vo=Vfb*(R1+R2)/R2 = Vfb(1+R1/R2)
- # R1/R2 = (Vo-Vfb)/Vfb
- # 3.3V/100mA Iq = 4μA
- # 1.3V: R1/R2 = 116K/100K
- # 1.4V: R1/R2 = 133K/100K
- # 0.925V: R1/R2 = 54K/100K
- 1.035M OHM
- 225K   OHM
- PD (100K)
- # Important: GPIO_DVFS /
  PMIC_STBY_REQ should be PULL DN
  when system reboot to ensure the
  VDD_ARM_SOC_IN voltage is not
  effected by DVFS
- PMIC_STBY_REQ = 0, GPIO_DVFS = 0, output is 1.4V (1.375V + 25mV)
  PMIC_STBY_REQ = 0, GPIO_DVFS = 1, output is 1.3V (1.275V + 25mV)
  PMIC_STBY_REQ = 1, GPIO_DVFS = 0, output is 0.925V (0.9V + 25mV)
- VDDHIGH / NVCC_xxx
- Current 2A
  I_Quiescent : 40μA
- ADC High PSRR
- # 2.5V-to-5.5V
- Vfb=0.6V
- # R1/R2 = 9/2
- # PG pin is pulled up to
  VIN by the internal
  resistor 500K OHM
- # Reset Button
- 1.8V PWR
- # Stitching CAP for Layout
- # RSV for eMMC HS200
- # 1.8V/200mA Iq = 1.2μA
- # GPIO/WDOG PWR OFF->ON
- LvDDR3
- NVCC_SD <SD3.0>
- Current 1A
  I_Quiescent : 40μA
- Vfb=1V
- # 1.8V/3.3V
- 499K
- 330K
- # Default: 3.3V
- # 2.5V to 6V
- Vfb=0.6V
- 160K
- # R1/R2 = 127K/100K
- # R1/R2 = (Vo-Vfb)/Vfb
- # FB = 0.8V
- # 1.8V: R1/R2 = 1/0.8 : 200K/160K
- # 3.3V: R1/R2 = 2.5/0.8 : 500K/160K
- # FB = 1.0V
- # 1.8V: R1/R2 = 0.8/ 1: 160K/200K
- # 3.3V: R1/R2 = 2.3/1 : 464K/200K
sheet 10
- TP for SODIMM MFG
- SODIMM 200
- CPU SODIMM TST/DBG
- BMOD TP for MFG TOOL
- # LCD_RST has been used as WDOG on CPU BOARD
- # Maxim DCDC_3V3 supply
  current for Base Board: 1.2A
sheet 11
- NOTE:
- All pins using ~reset as harden :
- PAD
- Default State
- Simulation Value
- UART3_TX_DATA
- Output Buffer(LOW) during reset --> Output keeper + Input enable after reset done
- 0 in real silicon
- LCD_DATA00~LCD_DATA23
- 100K pull down + input enable during reset --> Output keeper + Input enable
  after reset done ( this is boot option, we don’t need change)
- 0 in real silicon
- PAD
- Default State
- Signal Path
- PAD Simulation Value
- UART3_TX_DATA
- Output Buffer(LOW) during reset --> Output keeper + Input enable after reset done
- 0 in real silicon
- sjc.ipt_jta_active --> PAD
- (note : sjc.ipt_jta_active also connected
  to snvs_hp.sec_vio_in_1. This is security
  related, we don’t plan to change it.)
- ALT7
- All pins using ~src.en_system_clk as harden :
- PAD
- Default State
- Simulation Value
- GPIO1_IO03
- 100K pull down + input enable during reset --> Output keeper + Input enable
  after reset done
- 0 in real silicon
- PAD
- Default State
- Signal Path
- PAD Simulation Value
- GPIO1_IO03
- 100K pull down + input enable during reset --> Output keeper + Input enable after
  reset done
- PAD --> ccmsrcmix. src_tester_ack
- 0 in real silicon
- This is the requirement of TE test
- ALT7
- All pins using snvs_hp.snvs_sec_vio_in_5_en as harden :
- PAD
- Default State
- Simulation Value
- CSI_PIXCLK
- Output keeper + Input enable (snvs_sec_vio_in_5_en is 1’b0 in normal state,
  so harden is not triggerd in normal state). snvs_sec_vio_in_5_en is controlled
  by SNVS register. It can be disable or enable.
- X (0 or 1 in real silicon )
- DNP TABLE:
- REF DES
- ASSY_OPT
- PAGE NAME
- C227,C228
- DNP
- C-02 LvDDR3
- R308,R311,R312,U301A,U301B,
  U302
- DNP
- C-03 eMMC/NAND/TF/QSPI
- C414,C420,C421,C422,C423,R405
- DNP
- C-04 CPU PERI1
- C503,Q501,R501,R508,R513,
  R515,R517,R519,R520,Y503
- DNP
- C-05 CPU PERI2
- R601,R602,R603,R604,R605,
  R606,R607,R608,R609,R610,
  R611,R612,R614,R615,R616,
  R621,R622,R627,R628,R629,
  R630,R632,R635,R642,R655,R656
- DNP
- C-06 BOOT CFG
- C743,C744,C745,C746,C747,
  C819,C820,D701,R702,R703,
  R704,R705,R714,R716,R727,
  R731,R758
- DNP
- C-07 PWR MGR
- C807,C814
- DNP
- C-08 SODIMM
